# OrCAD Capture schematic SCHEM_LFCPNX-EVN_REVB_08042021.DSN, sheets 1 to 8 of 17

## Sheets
1 Title Page: title: Title Page; rev: 1.0; note: 305-PD-21-0742
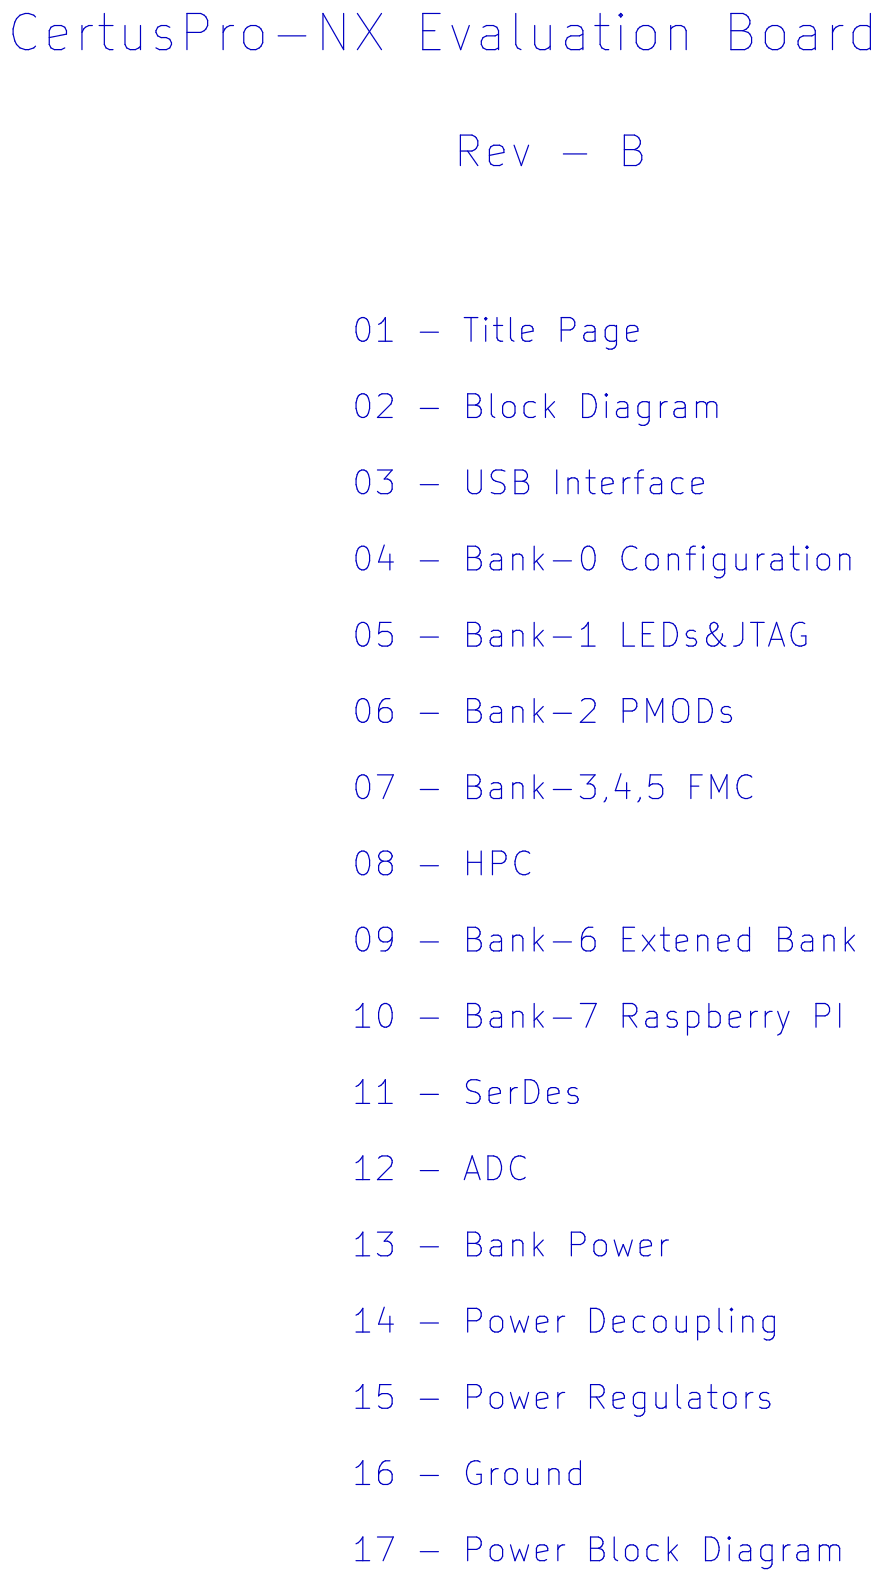
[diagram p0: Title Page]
2 Block Diagram: title: Block Diagram
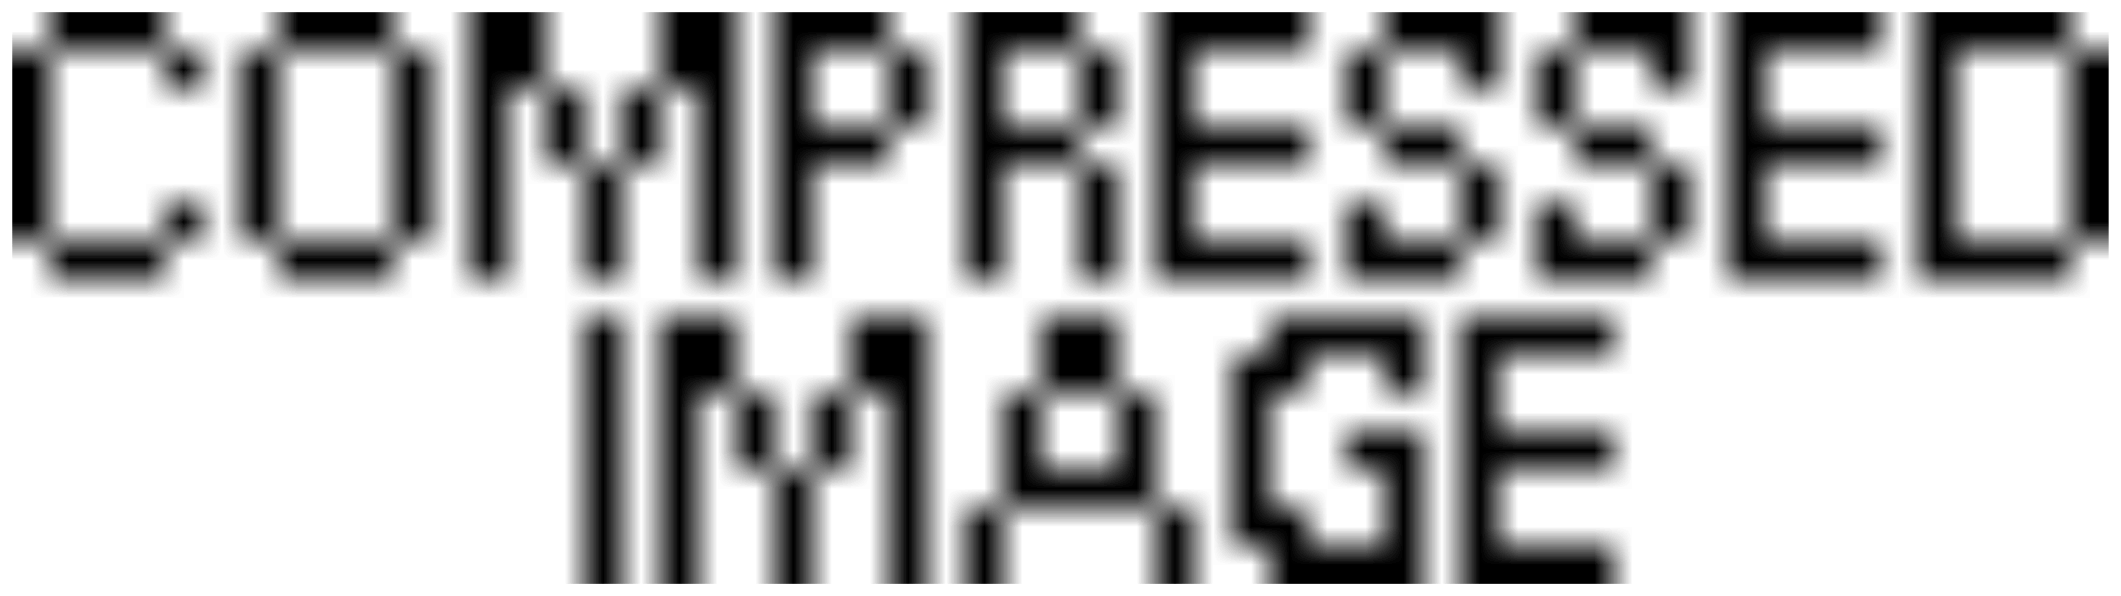
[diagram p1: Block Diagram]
3 USB Interface: size B; title: USB Interface
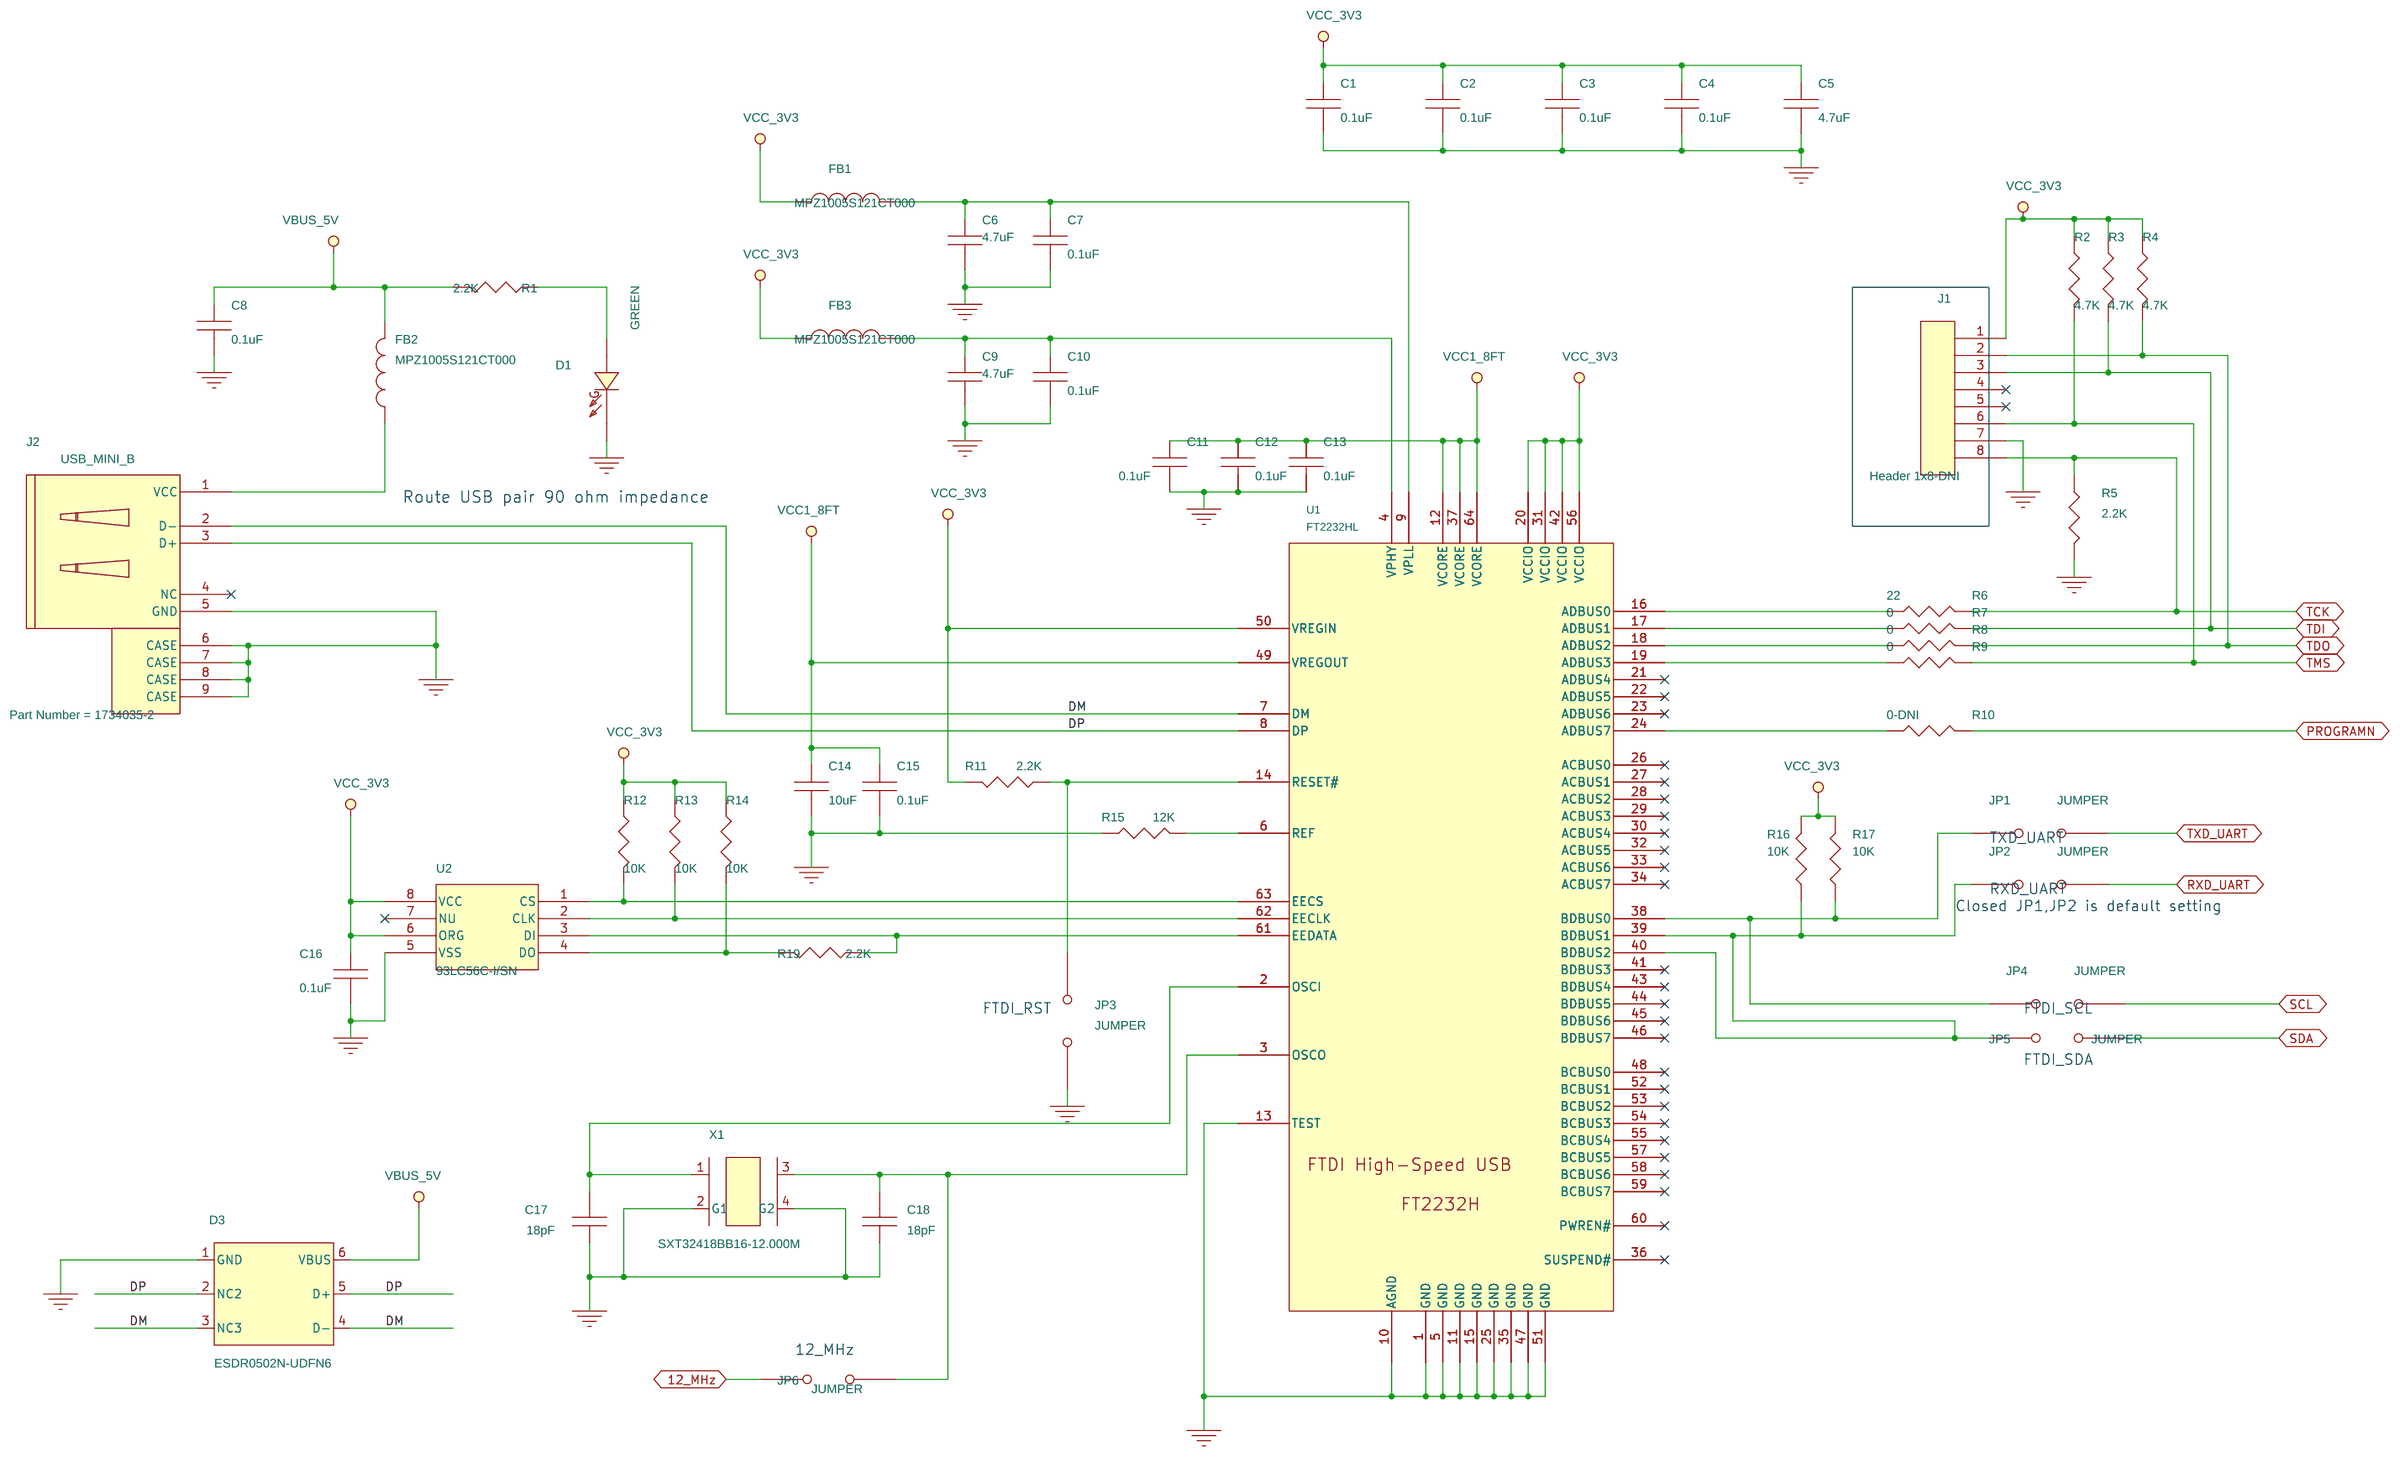
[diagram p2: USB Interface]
4 Bank-0 Configuration: size B; title: Bank-0 Configuration
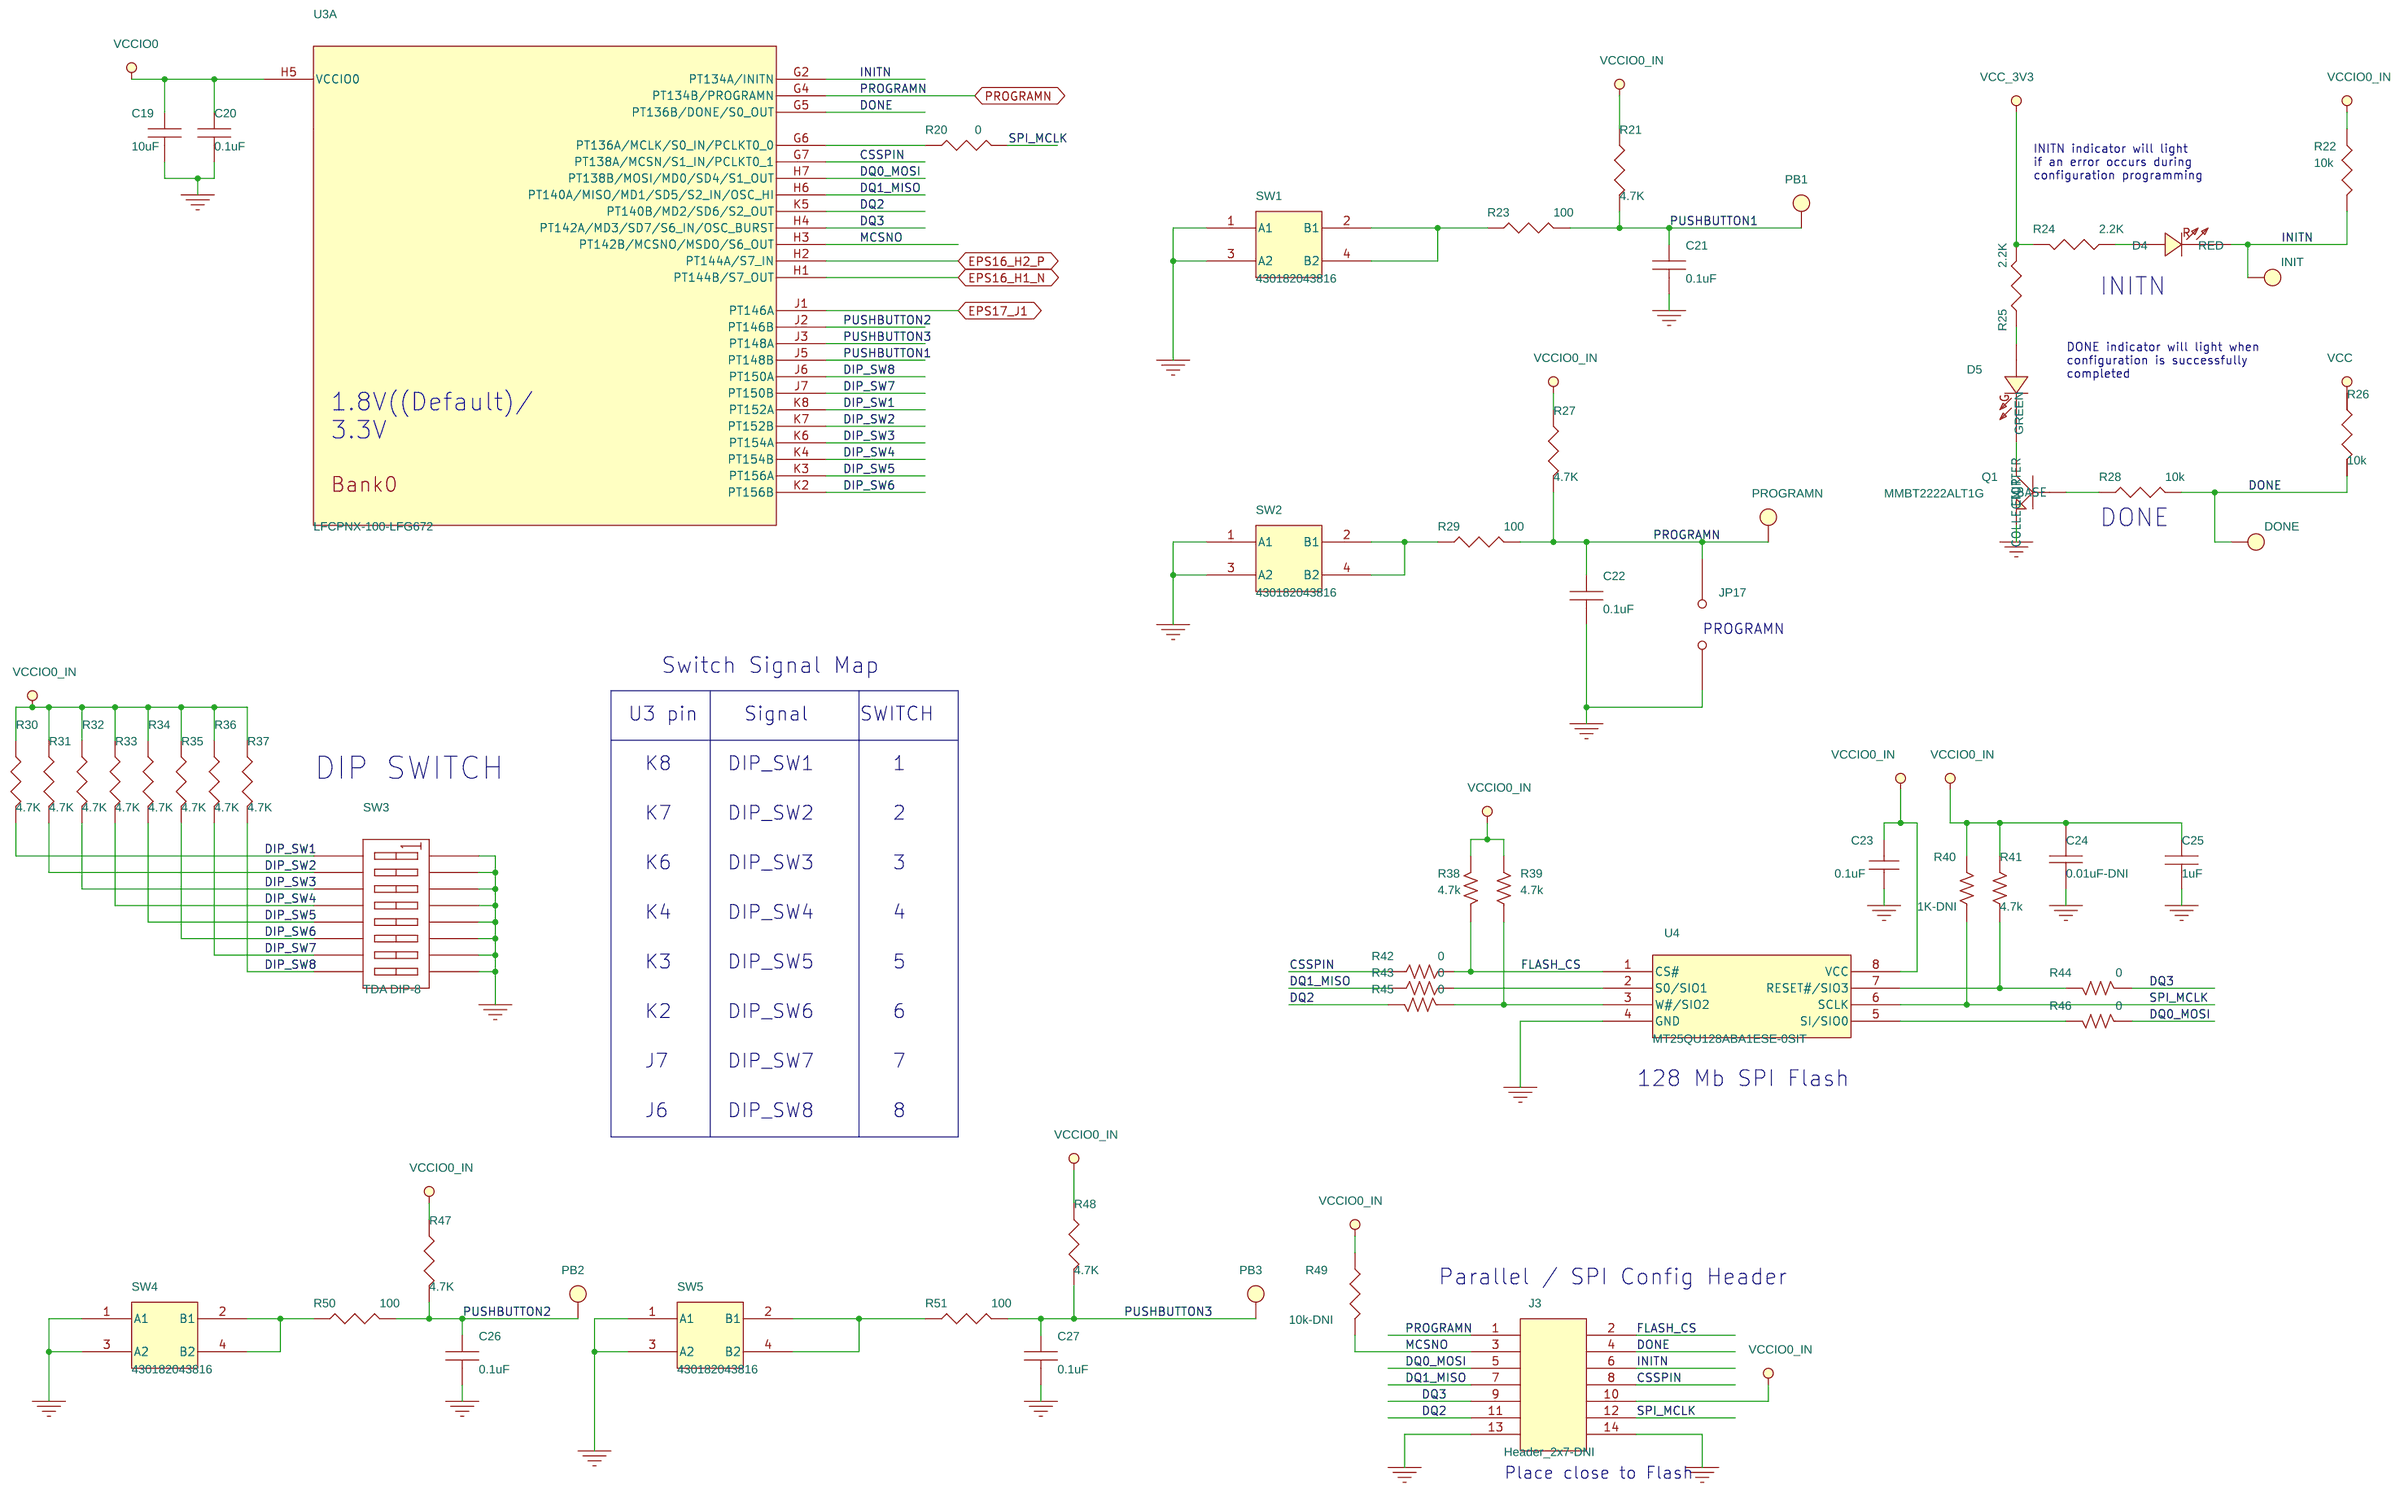
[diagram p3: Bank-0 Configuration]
5 Bank-1 LEDst&JTAG: size B; title: Bank-1 LEDs&JTAG
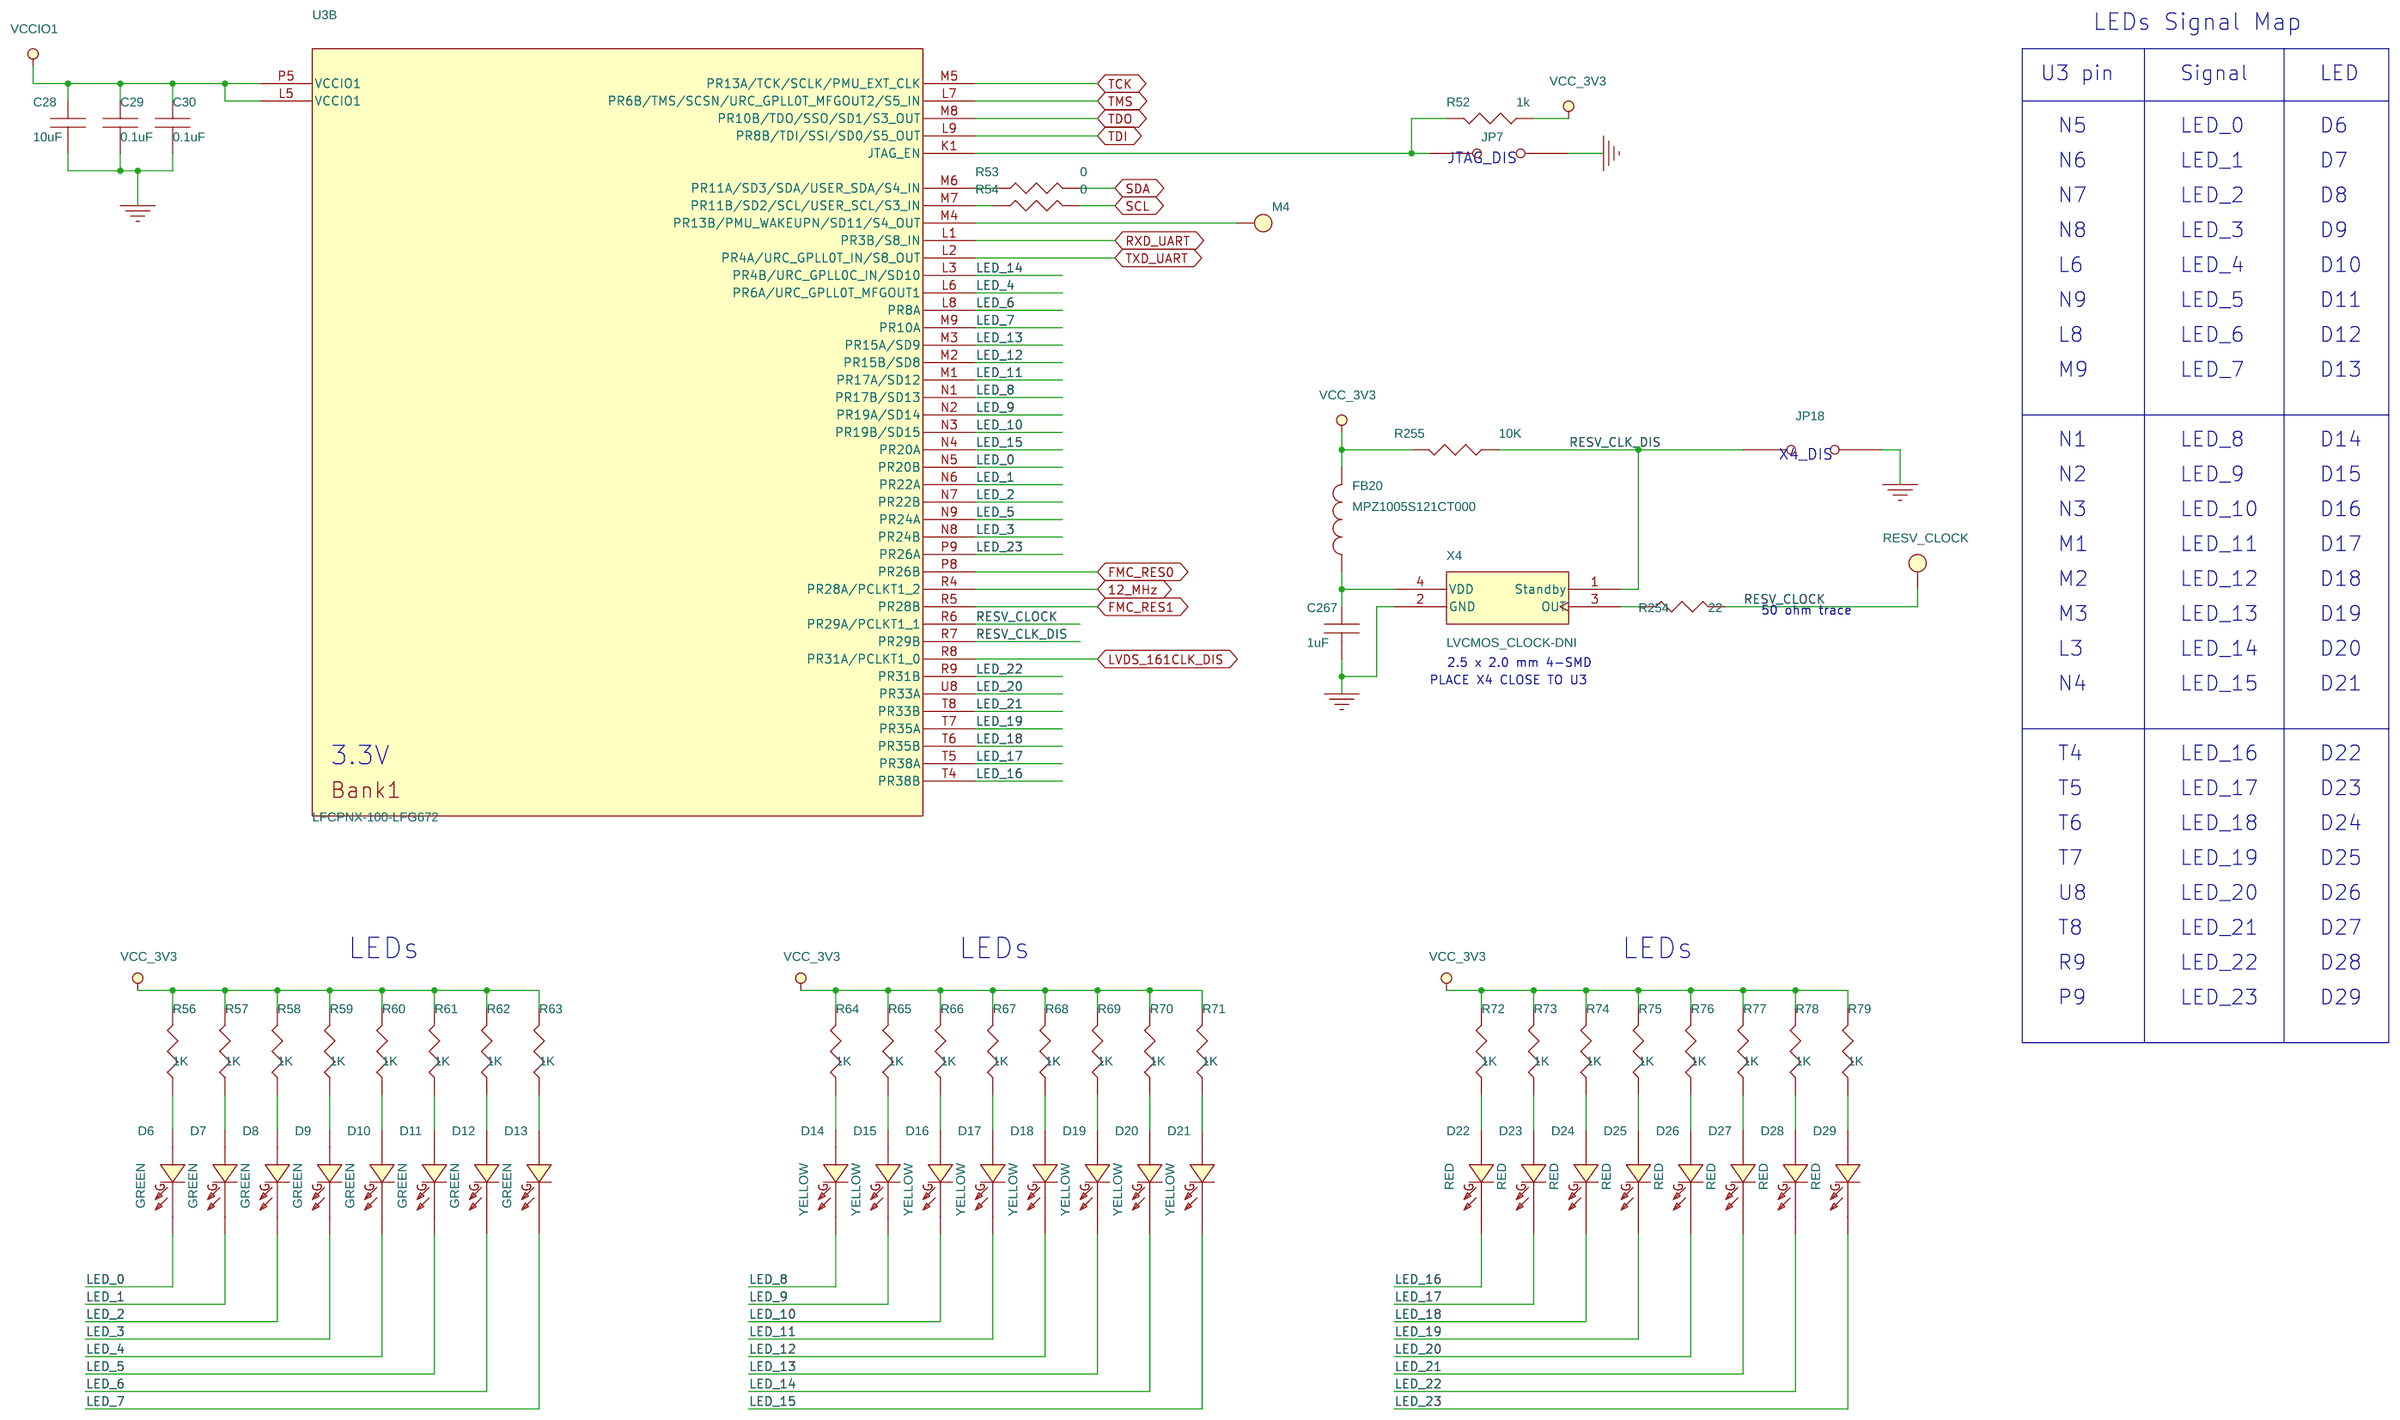
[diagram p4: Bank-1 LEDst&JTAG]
6 Bank-2 PMODs: size B; title: Bank-2 PMODs
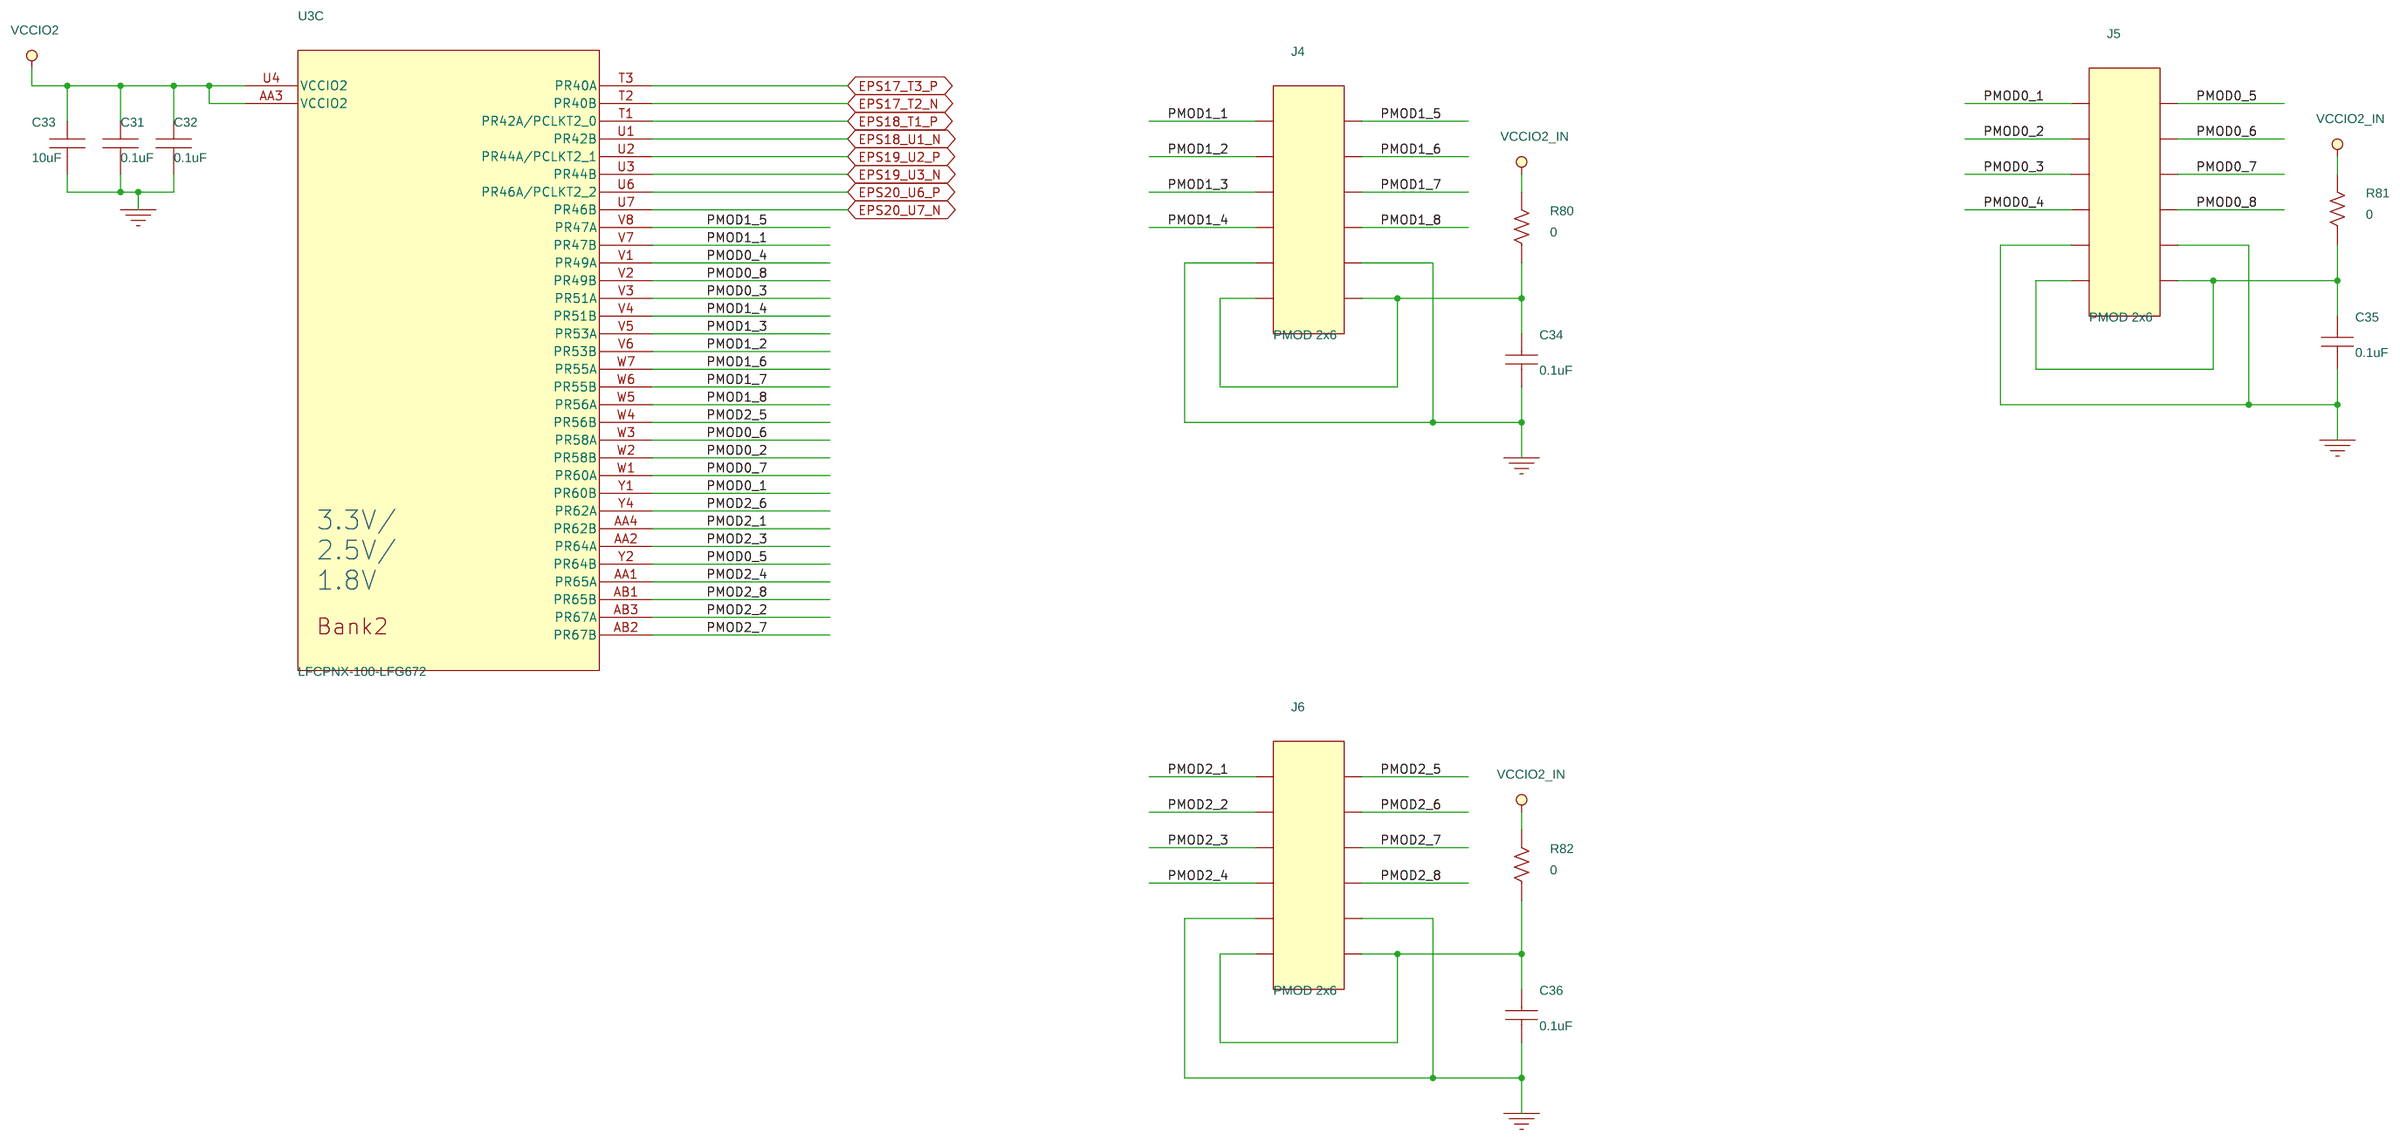
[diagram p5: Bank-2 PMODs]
7 Bank-3,4,5 FMC: size C; title: Bank-3,4,5 FMC
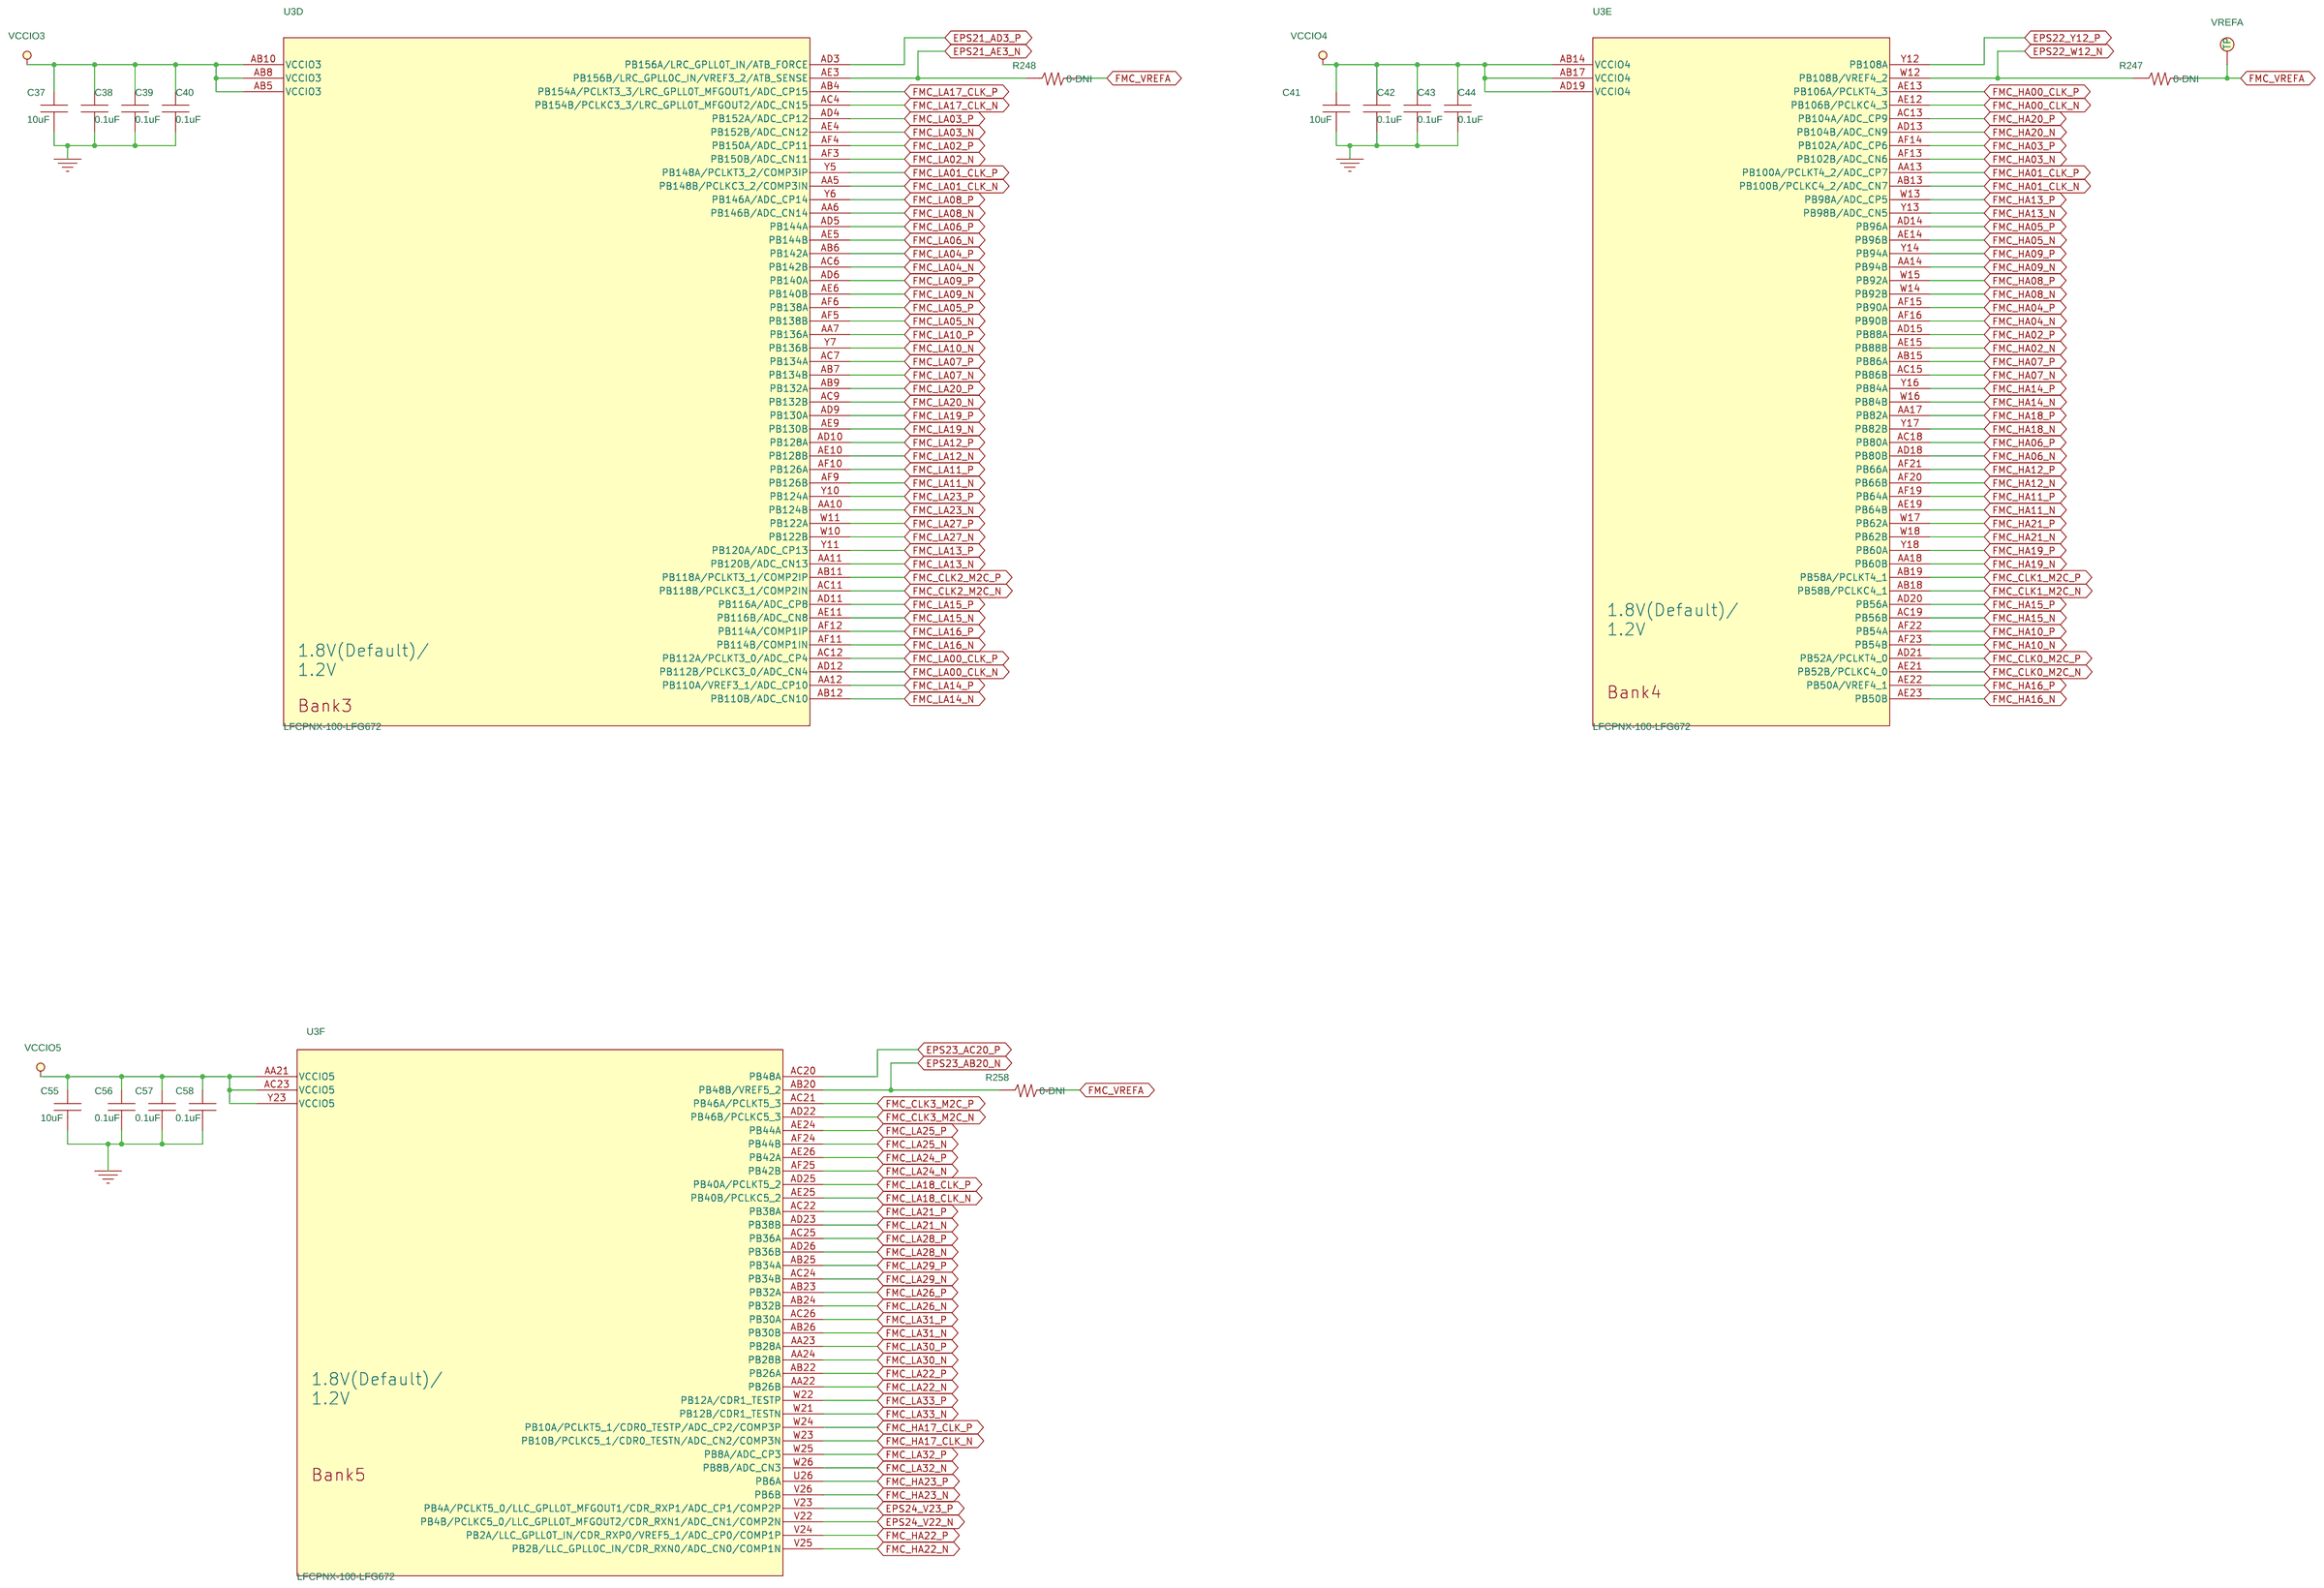
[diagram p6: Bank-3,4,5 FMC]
8 HPC: size C; title: HPC
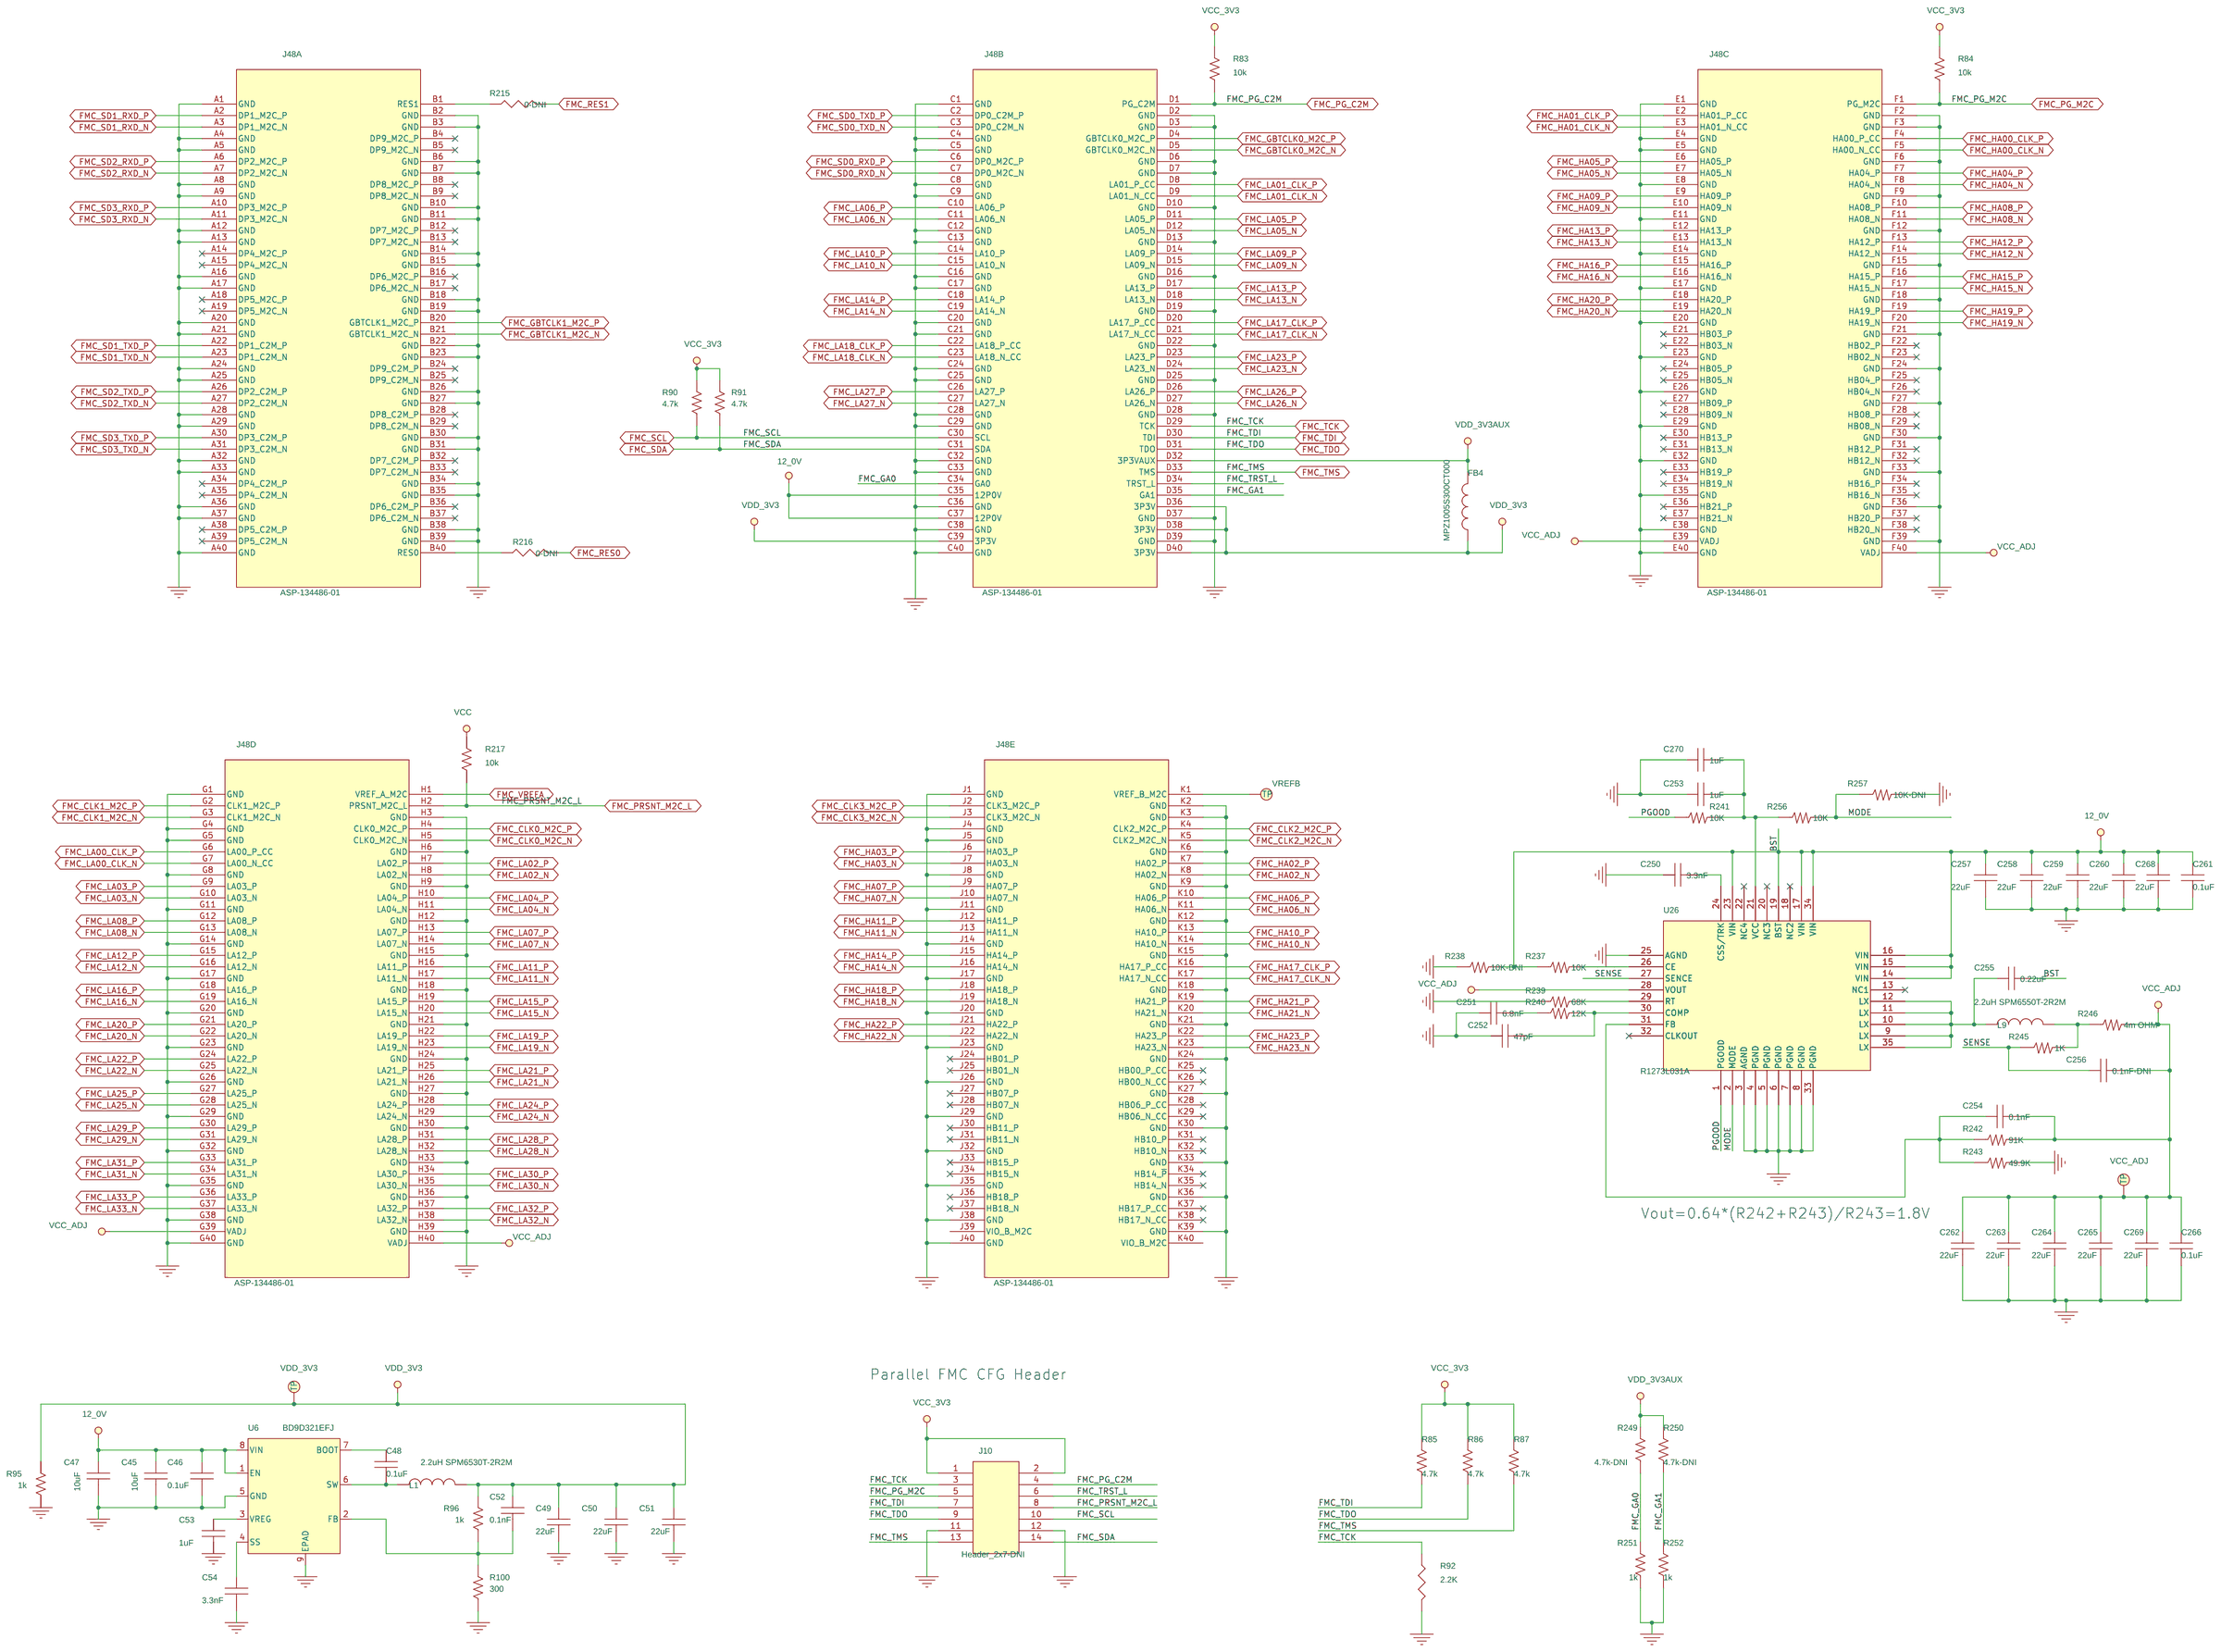
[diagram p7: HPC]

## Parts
sheet Bank-0 Configuration
C19  10uF  [C0402]
C20  0.1uF  [C0201]
C21  0.1uF  [C0201]
C22  0.1uF  [C0201]
C23  0.1uF  [C0201]
C24  0.01uF-DNI  [C0402]
C25  1uF  [C0603]
C26  0.1uF  [C0201]
C27  0.1uF  [C0201]
D4  RED  [APT1608]
D5  GREEN  [APT1608]
DONE  TestPoint  [TP50]
INIT  TestPoint  [TP50]
J3  Header_2x7-DNI  [Header_2x7]
JP17  JUMPER  [Header_1x2]
PB1  TestPoint_SMT  [TPC32]
PB2  TestPoint_SMT  [TPC32]
PB3  TestPoint_SMT  [TPC32]
PROGRAMN  TestPoint_SMT  [TPC32]
Q1  MMBT2222ALT1G  [MMBT2222ALT-1]
R20  0  [R0402]
R21  4.7K  [R0603]
R22  10k  [R0603]
R23  100  [R0402]
R24  2.2K  [R0603]
R25  2.2K  [R0603]
R26  10k  [R0603]
R27  4.7K  [R0603]
R28  10k  [R0603]
R29  100  [R0402]
R30  4.7K  [R0603]
R31  4.7K  [R0603]
R32  4.7K  [R0603]
R33  4.7K  [R0603]
R34  4.7K  [R0603]
R35  4.7K  [R0603]
R36  4.7K  [R0603]
R37  4.7K  [R0603]
R38  4.7k  [R0603]
R39  4.7k  [R0603]
R40  1K-DNI  [R0603]
R41  4.7k  [R0603]
R42  0  [R0402]
R43  0  [R0402]
R44  0  [R0402]
R45  0  [R0402]
R46  0  [R0402]
R47  4.7K  [R0603]
R48  4.7K  [R0603]
R49  10k-DNI  [R0603]
R50  100  [R0402]
R51  100  [R0402]
SW1  430182043816  [430182043816]
SW2  430182043816  [430182043816]
SW3  TDA DIP-8  [TDA08H0SB1]
SW4  430182043816  [430182043816]
SW5  430182043816  [430182043816]
U4  MT25QU128ABA1ESE-0SIT  [SO8_MX25L12833FM2I10G]
sheet Bank-1 LEDst&JTAG
C28  10uF  [C0402]
C29  0.1uF  [C0201]
C30  0.1uF  [C0201]
C267  1uF  [C0603]
D6  GREEN  [APT1608]
D7  GREEN  [APT1608]
D8  GREEN  [APT1608]
D9  GREEN  [APT1608]
D10  GREEN  [APT1608]
D11  GREEN  [APT1608]
D12  GREEN  [APT1608]
D13  GREEN  [APT1608]
D14  YELLOW  [APT1608]
D15  YELLOW  [APT1608]
D16  YELLOW  [APT1608]
D17  YELLOW  [APT1608]
D18  YELLOW  [APT1608]
D19  YELLOW  [APT1608]
D20  YELLOW  [APT1608]
D21  YELLOW  [APT1608]
D22  RED  [APT1608]
D23  RED  [APT1608]
D24  RED  [APT1608]
D25  RED  [APT1608]
D26  RED  [APT1608]
D27  RED  [APT1608]
D28  RED  [APT1608]
D29  RED  [APT1608]
FB20  MPZ1005S121CT000  [FB0402]
JP7  JUMPER  [Header_1x2]
JP18  JUMPER  [Header_1x2]
M4  TestPoint_SMT  [TPC32]
R52  1k  [R0603]
R53  0  [R0402]
R54  0  [R0402]
R56  1K  [R0603]
R57  1K  [R0603]
R58  1K  [R0603]
R59  1K  [R0603]
R60  1K  [R0603]
R61  1K  [R0603]
R62  1K  [R0603]
R63  1K  [R0603]
R64  1K  [R0603]
R65  1K  [R0603]
R66  1K  [R0603]
R67  1K  [R0603]
R68  1K  [R0603]
R69  1K  [R0603]
R70  1K  [R0603]
R71  1K  [R0603]
R72  1K  [R0603]
R73  1K  [R0603]
R74  1K  [R0603]
R75  1K  [R0603]
R76  1K  [R0603]
R77  1K  [R0603]
R78  1K  [R0603]
R79  1K  [R0603]
R254  22  [R0402]
R255  10K  [R0603]
RESV_CLOCK  TestPoint_SMT  [TPC32]
X4  LVCMOS_CLOCK-DNI  [ASFLMB_125_000MHZ-LR-T]
sheet Bank-2 PMODs
C31  0.1uF  [C0201]
C32  0.1uF  [C0201]
C33  10uF  [C0402]
C34  0.1uF  [C0201]
C35  0.1uF  [C0201]
C36  0.1uF  [C0201]
J4  PMOD 2x6  [PPPC062LJBN-RC]
J5  PMOD 2x6  [PPPC062LJBN-RC]
J6  PMOD 2x6  [PPPC062LJBN-RC]
R80  0  [R0603]
R81  0  [R0603]
R82  0  [R0603]
sheet Bank-3,4,5 FMC
C37  10uF  [C0402]
C38  0.1uF  [C0201]
C39  0.1uF  [C0201]
C40  0.1uF  [C0201]
C41  10uF  [C0402]
C42  0.1uF  [C0201]
C43  0.1uF  [C0201]
C44  0.1uF  [C0201]
C55  10uF  [C0402]
C56  0.1uF  [C0201]
C57  0.1uF  [C0201]
C58  0.1uF  [C0201]
R247  0-DNI  [R0603]
R248  0-DNI  [R0603]
R258  0-DNI  [R0603]
VREFA  TP_S_40_63  [tp_s_40_63]
sheet Bank-7 Raspberry PI
U3  LFCPNX-100-LFG672  [BGA672-1P0]  (sections A,B,C,D,E,F,G,H,I,J,K,L,M,N)
sheet HPC
C45  10uF  [C1206]
C46  0.1uF  [C0201]
C47  10uF  [C1206]
C48  0.1uF  [C0201]
C49  22uF  [C0603]
C50  22uF  [C0603]
C51  22uF  [C0603]
C52  0.1nF  [C0603]
C53  1uF  [C0603]
C54  3.3nF  [C0201]
C250  3.3nF  [C0201]
C251  6.8nF  [C0603]
C252  47pF  [C0603]
C253  1uF  [C0603]
C254  0.1nF  [C0603]
C255  0.22uF  [C0603]
C256  0.1nF-DNI  [C0603]
C257  22uF  [C0805]
C258  22uF  [C0805]
C259  22uF  [C0805]
C260  22uF  [C0805]
C261  0.1uF  [C0201]
C262  22uF  [C0603]
C263  22uF  [C0603]
C264  22uF  [C0603]
C265  22uF  [C0603]
C266  0.1uF  [C0201]
C268  22uF  [C0805]
C269  22uF  [C0603]
C270  1uF  [C0603]
FB4  MPZ1005S300CT000  [FB0402]
J10  Header_2x7-DNI  [Header_2x7]
J48  ASP-134486-01  [ASP-134486-01]  (sections A,B,C,D,E)
L1  2.2uH SPM6530T-2R2M  [SPM6530T-2R2M]
L9  2.2uH SPM6550T-2R2M  [SPM6550T-2R2M]
R83  10k  [R0603]
R84  10k  [R0603]
R85  4.7k  [R0603]
R86  4.7k  [R0603]
R87  4.7k  [R0603]
R90  4.7k  [R0603]
R91  4.7k  [R0603]
R92  2.2K  [R0603]
R95  1k  [R0603]
R96  1k  [R0603]
R100  300  [R0402]
R215  0-DNI  [R0603]
R216  0-DNI  [R0603]
R217  10k  [R0603]
R237  10K  [R0603]
R238  10K-DNI  [R0603]
R239  68K  [R0603]
R240  12K  [R0603]
R241  10K  [R0603]
R242  91K  [R0603]
R243  49.9K  [R0603]
R245  1K  [R0603]
R246  4m OHM  [R1206]
R249  4.7k-DNI  [R0603]
R250  4.7k-DNI  [R0603]
R251  1k  [R0603]
R252  1k  [R0603]
R256  10K  [R0603]
R257  10K-DNI  [R0603]
U6  BD9D321EFJ  [HTSOP_8_BD9D321]
U26  R1273L031A  [QFN0505_32B]
VCC_ADJ  TP_S_40_63  [tp_s_40_63]
VDD_3V3  TP_S_40_63  [tp_s_40_63]
VREFB  TP_S_40_63  [tp_s_40_63]
sheet USB Interface
C1  0.1uF  [C0201]
C2  0.1uF  [C0201]
C3  0.1uF  [C0201]
C4  0.1uF  [C0201]
C5  4.7uF  [C0603]
C6  4.7uF  [C0603]
C7  0.1uF  [C0201]
C8  0.1uF  [C0201]
C9  4.7uF  [C0603]
C10  0.1uF  [C0201]
C11  0.1uF  [C0201]
C12  0.1uF  [C0201]
C13  0.1uF  [C0201]
C14  10uF  [C0402]
C15  0.1uF  [C0201]
C16  0.1uF  [C0201]
C17  18pF  [C0402]
C18  18pF  [C0402]
D1  GREEN  [APT1608]
D3  ESDR0502N-UDFN6  [UDFN6_040]
FB1  MPZ1005S121CT000  [FB0402]
FB2  MPZ1005S121CT000  [FB0402]
FB3  MPZ1005S121CT000  [FB0402]
J1  Header 1x8-DNI  [hdr_amp_87220_8_1x8_100]
J2  USB_MINI_B  [USB_MINI_B-1734035-2]
JP1  JUMPER  [Header_1x2]
JP2  JUMPER  [Header_1x2]
JP3  JUMPER  [Header_1x2]
JP4  JUMPER  [Header_1x2]
JP5  JUMPER  [Header_1x2]
JP6  JUMPER  [Header_1x2]
R1  2.2K  [R0603]
R2  4.7K  [R0603]
R3  4.7K  [R0603]
R4  4.7K  [R0603]
R5  2.2K  [R0603]
R6  22  [R0402]
R7  0  [R0402]
R8  0  [R0402]
R9  0  [R0402]
R10  0-DNI  [R0402]
R11  2.2K  [R0603]
R12  10K  [R0603]
R13  10K  [R0603]
R14  10K  [R0603]
R15  12K  [R0603]
R16  10K  [R0603]
R17  10K  [R0603]
R19  2.2K  [R0603]
U1  FT2232HL  [tqfp64_0p5_12p2x12p2_h1p6]
U2  93LC56C-I/SN  [so8_50_244]
X1  SXT32418BB16-12.000M  [xtal_4p_SXT32418BB16_12000M]

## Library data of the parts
C19 C28 C33 C37 C41 C55 = 10uF_0603
C1-C5 C7 C8 C10-C13 C16 C20 C25 C29-C32 C38-C40 C42-C44 C46 C48 C56-C58 = 0u1_0402: CAP CER 0.1UF 25V 10% X5R 0201; Manufacturer: Murata; Manufacturer Part Number: GRM033R61E104KE14J
C15 C21 C22 C26 C27 C261 C266 C267 = 0u1_0402: CAP CER 0.1UF 16V 10% X7R 0402
C23 = CAP_NP: COMPFIXED: NO; COMPGROUP: 0; COMPHEIGHT: 0.000; COMPKEY: NO; COMPLOC: [1820.000,2015.000]; COMPLOCKED: NO; COMPROT: 270; COMPSIDE: TOP; DECOUPLER: NO; FPLIST: SM/C_0402; MEMORY: NO
C24 = CAP_1
D4 = LED-SMT1206_RED_0
D1 D5-D29 = LED-SMT1206_GREEN_1
DONE INIT M4 = T_POINT_R
J3 = Header_2x7: Assy: DNL
JP1-JP7 JP17 JP18 = JUMPER_0
PB1-PB3 PROGRAMN RESV_CLOCK = T_POINT_R: Assy: DNI
Q1 = 2N2222
R20 R53 R54 = R: RES SMD 33 OHM 1% 1/10W 0402; Manufacturer: Panasonic; Manufacturer Part Number: ERJ-2RKF33R0X
R2-R4 R21 R27 R30-R37 R47 R48 = 5k1_0402: RES 4.70K OHM 1/10W 1% 0603 SMD; Digikey P/N: 541-4.70KHTR-ND; Manufacturer: Vishay; Manufacturer Part Number: CRCW06034K70FKEA
R22 R26 R49 = R: RES SMD 10K OHM 1% 1/16W 0402; MFG: Yageo; MFG P/N: RC0402FR-0710KL; Manufacturer: Yageo; Manufacturer Part Number: RC0402FR-0710KL
R23 R29 R50 R51 = RES_10K_1W16_0402_5P: RES SMD 100 OHM 1% 1/10W 0402; Digikey P/N: RMCF0603JT10K0TR-ND; MFG: Pansonic; MFG P/N: ERJ-2RKF1000X; Manufacturer: Pansonic; Manufacturer Part Number: ERJ-2RKF1000X; Wattage: 1/10W
R24 R25 = RES_0: RES SMD 1K OHM 1% 1/10W 0402; Manufacturer: Panasonic; Manufacturer Part Number: ERJ-2RKF1001X
R28 = RES_0: RES SMD 10K OHM 1% 1/16W 0402; MFG: Yageo; MFG P/N: RC0402FR-0710KL; Manufacturer: Yageo; Manufacturer Part Number: RC0402FR-0710KL
R38 R39 R41 R83-R87 R91 R95 R96 R217 R249-R252 = R_v3: RES SMD 4.7K OHM 5% 1/10W 0402; COMPFIXED: NO; COMPGROUP: 0; COMPHEIGHT: 0.000; COMPKEY: NO; COMPLOC: [970.000,1160.000]; COMPLOCKED: NO; COMPROT: 180; COMPSIDE: TOP; DECOUPLER: NO; FPLIST: AX/RC05,SM/R_0603; MEMORY: NO; MFG: Panasonic; MFG P/N: ERJ-2GEJ472X; Manufacturer: Panasonic; Manufacturer Part Number: ERJ-2GEJ472X
R40 = R_v3: RES SMD 1K OHM 1% 1/10W 0402; Assy: DNI; COMPFIXED: NO; COMPGROUP: 0; COMPHEIGHT: 0.000; COMPKEY: NO; COMPLOC: [970.000,1160.000]; COMPLOCKED: NO; COMPROT: 180; COMPSIDE: TOP; DECOUPLER: NO; FPLIST: AX/RC05,SM/R_0603; MEMORY: NO; Manufacturer: Panasonic; Manufacturer Part Number: ERJ-2RKF1001X
R42-R46 = R_v3: RES SMD 0.0OHM JUMPER 1/10W 0402; COMPFIXED: NO; COMPHEIGHT: 0.000; COMPKEY: NO; COMPLOC: [3325.000,1400.000]; COMPLOCKED: NO; COMPROT: 180; COMPSIDE: TOP; DECOUPLER: NO; FPLIST: AX/RC05; MEMORY: NO; Manufacturer: Panasonic; Manufacturer Part Number: ERJ-2GE0R00X
SW1 SW2 SW4 SW5 = EVQP0_0: SWITCH TACTILE SPST-NO 0.05A 12V; Cost Ea/1k: $ 0.11025 (1000-4999), 0.09135 (5000+); Digikey P/N: CKN9112TR-ND; Distributor: Digi-Key; MFG: C&K Components; Manufacturer: C&K Components
SW3 = SW_DIP-8
U4 = N25QxxxA13xF8_0: IC FLASH 128MBIT 104MHZ 8SOP; Manufacturer: Macronix; Manufacturer Part Number: MX25L12833FM2I-10G; Populate: DI
FB1-FB3 FB20 = INDUCTOR_1: FERRITE BEAD 120 OHM 0402 1LN; Manufacturer: TDK Corporation
R52 = RES_100K_1W16_0402_5P: RES 100K OHM 1/10W 1% 0402 SMD; MFG: Panasonic; MFG P/N: ERJ-2RKF1003X; Manufacturer: Panasonic; Manufacturer Part Number: ERJ-2RKF1003X; PART_NUMBER: ERJ-2RKF1003X
R56-R79 = 1k_0402: RES 1K OHM 1/10W 1% 0603 SMD; Digikey P/N: 311-1.00KHRCT-ND; Manufacturer Part Number: RC0603FR-071KL
R254 = 1R_0.25W_0603: Manufacturer: Vishay
R255 = RESISTOR: RES 10K OHM 1/10W 5% 0603
X4 = ASDMB: MEMS OSC XO 125.0000MHZ LVCMOS; Assy: DNI; Manufacturer: Abracon LLC
C34-C36 = C0402C104K4RACTU: CAP CER 0.1UF 25V 10% X5R 0201; Manufacturer: Murata; Manufacturer Part Number: GRM033R61E104KE14J
J4-J6 = SKT2x6_PPPC062LFBN-RC: CONN HDR 12POS 0.1 GOLD PCB R/A; Manufacturer: Sullins
R80-R82 = R_v3: COMPFIXED: NO; COMPHEIGHT: 0.000; COMPKEY: NO; COMPLOC: [970.000,1160.000]; COMPLOCKED: NO; COMPROT: 180; COMPSIDE: TOP; DECOUPLER: NO; FPLIST: AX/RC05,SM/R_0603; MEMORY: NO; Tollerance: 1%
R237-R243 R245-R248 R256-R258 = R_v2: COMPFIXED: 1%
VCC_ADJ VDD_3V3 VREFA VREFB = TP_S_40_63: Assy: DNI
U3 = LFCPNX100K-FFG672
C45 C47 = 10uF_0603: CAP CER 10UF 25V X5R 1206; Manufacturer Part Number: TMK316BJ106KL-T
C49-C51 C262-C265 C269 = 10uF_0603: CAP CER 22UF 10V X5R 0603; Manufacturer: Murata; Manufacturer Part Number: GRM188R61A226ME15D
C52 = 10uF_0603: CAP CER 100PF 50V C0G/NPO 0603; Manufacturer: Yageo; Manufacturer Part Number: CC0603JRNPO9BN101
C53 = 10uF_0603: CAP CER 1UF 25V 10% X7R 0603; Manufacturer Part Number: TMK107B7105KA-T
C54 C250 C254 = 0u1_0402: CAP CER 3300PF 25V X7R 0201; Manufacturer: Murata; Manufacturer Part Number: GRM033R71E332KA12D
C251 = 0u1_0402: CAP CER 6800PF 50V C0G 0603; Digikey P/N: 445-6914-2-ND; Manufacturer: Murata; Manufacturer Part Number: GRM033R71E332KA12D
C252 = 0u1_0402: CAP CER 47PF 50V C0G 0603; Manufacturer: Murata; Manufacturer Part Number: CAP CER 47PF 50V C0G 0603
C253 C270 = 0u1_0402: CAP CER 1UF 25V 10% X7R 0603; Manufacturer: Murata; Manufacturer Part Number: TMK107B7105KA-T
C255 = 0u1_0402: CAP CER 0.22UF 25V X7R 0603; Manufacturer: Murata; Manufacturer Part Number: GCM188R71E224KA55D
C256 = 0u1_0402: CAP CER 100PF 50V C0G/NPO 0603; Manufacturer: Murata; Manufacturer Part Number: CC0603JRNPO9BN101
C257-C260 C268 = 0u1_0402: CAP CER GRT21BR61E226ME13L; Digikey P/N: 490-12389-2-ND; Manufacturer: Murata; Manufacturer Part Number: GRT21BR61E226ME13L
FB4 = INDUCTOR_1: FERRITE BEAD 120 OHM 0402 1LN; Manufacturer: TDK Corporation; Manufacturer Part Number: MPZ1005S121CT000
J10 = Header_2x7
J48 = ASP-134486-01
L1 L9 = INDUCTOR_0
R90 = R_v3: RES SMD 1K OHM 1% 1/10W 0402; COMPFIXED: NO; COMPGROUP: 0; COMPHEIGHT: 0.000; COMPKEY: NO; COMPLOC: [970.000,1160.000]; COMPLOCKED: NO; COMPROT: 180; COMPSIDE: TOP; DECOUPLER: NO; FPLIST: AX/RC05,SM/R_0603; MEMORY: NO; Manufacturer: Panasonic; Manufacturer Part Number: ERJ-2RKF1001X
R5 R11 R92 R215 R216 = 5k1_0402: Digikey P/N: 541-2.20KHTR-ND; Manufacturer: Vishay; Manufacturer Part Number: CRCW06032K20FKEA
R100 = R_v3: RES SMD 300 OHM 1% 1/10W 0402; COMPFIXED: NO; COMPGROUP: 0; COMPHEIGHT: 0.000; COMPKEY: NO; COMPLOC: [970.000,1160.000]; COMPLOCKED: NO; COMPROT: 180; COMPSIDE: TOP; DECOUPLER: NO; FPLIST: AX/RC05,SM/R_0603; MEMORY: NO; MFG: Panasonic; MFG P/N: ERJ-2RKF3000X; Manufacturer: Panasonic; Manufacturer Part Number: ERJ-2RKF3000X
U6 = BD9D321EFJ
U26 = R1273L
C6 C9 = 4u7_0603: CAP CER 4.7UF 6.3V 10% X5R 0603; Digikey P/N: PCC2396CT-ND
C14 = 10uF_0603: CAP CER 10UF 10V 20% X5R 0603
C17 C18 = 0u1_0402: CAP CER 18PF 25V 10% NP0 0402; Digikey P/N: C0402C180K3GACTU-ND; Manufacturer Part Number: C0402C180K3GACTU
D3 = ESDR0502: Manufacturer: Semtech; Manufacturer Part Number: RClamp0524P
J1 = header1x8_100: CONN HEADER 8POS .100 VERT TIN; Assy: DNI; Digikey P/N: WM50017-08-ND; Manufacturer Part Number: 0022284081
J2 = USB_MINI_B_0: CONN RCPT USB2.0 MINI B SMD R/A; COMPFIXED: NO; COMPGROUP: 0; COMPHEIGHT: 0.000; COMPKEY: NO; COMPLOC: [370.000,2590.000]; COMPLOCKED: NO; COMPROT: 270; COMPSIDE: TOP; DECOUPLER: NO; FPLIST: TYPE_B; MEMORY: NO; Manufacturer: TE Connectivity AMP Connectors; Manufacturer Part Number: 1734035-2; Part Number: 1734035-2; Populate: <Populate>
R1 R15 R19 = 10k_0402: RES 12K OHM 1/10W 1% 0603 SMD; Digikey P/N: 311-12.0KHRTR-ND; Manufacturer Part Number: RC0603FR-0712KL; Tolerance: 1%
R6 = 0R_0603: RES SMD 33 OHM 1% 1/10W 0402; Manufacturer: Panasonic; Manufacturer Part Number: ERJ-2RKF33R0X
R7-R9 = 0R_0603: RES 0.0 OHM 1/10W JUMP 0603 SMD
R10 = 0R_0603: RES SMD 1K OHM 1% 1/10W 0603; Assy: DNI; Manufacturer Part Number: RC0603FR-071KL
R12-R14 = RES_10K_1W16_0402_5P: RES 10K OHM 1/10W 5% 0603; Digikey P/N: RMCF0603JT10K0TR-ND; Manufacturer: Stackpole Electronics Inc; Manufacturer Part Number: RMCF0603JT10K0; Wattage: 1/10W
R16 R17 = RESISTOR: Populate: <Populate>
U1 = FT2232HL: IC USB HS DUAL UART/FIFO 64-LQFP; Assy: Customer Supplied
U2 = 93LC56_SO8_0: IC EEPROM 2KBIT 3MHZ 8SOIC
X1 = crystal-3p2x2p5: CRYSTAL 12MHZ 18PF SMD; Manufacturer: Suntsu Electronics, Inc.

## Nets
GND: C1.2 C2.2 C3.2 C4.2 C5.2 C6.2 C7.2 C8.2 C9.2 C10.2 C11.2 C12.2 C13.2 C14.2 C15.2 C16.2 C17.1 C18.1 C19.2 C20.2 C21.2 C22.2 C23.1 C24.2 C25.2 C26.2 C27.2 C28.2 C29.2 C30.2 C31.2 C32.2 C33.2 C34.2 C35.2 C36.2 C37.2 C38.2 C39.2 C40.2 C41.2 C42.2 C43.2 C44.2 C45.2 C46.2 C47.2 C49.2 C50.2 C51.2 C53.2 C54.2 C55.2 C56.2 C57.2 C58.2 C250.1 C251.1 C252.1 C253.1 C257.2 C258.2 C259.2 C260.2 C261.2 C262.2 C263.2 C264.2 C265.2 C266.2 C267.2 C268.2 C269.2 C270.1 D1.1(CATHODE) D3.1(GND) J1.7 J2.5(GND) J2.6(CASE) J2.7(CASE) J2.8(CASE) J2.9(CASE) J3.13 J3.14 J4.5 J4.11 J5.5 J5.11 J6.5 J6.11 J10.11 J10.12 J48.A1(GND) J48.A4(GND) J48.A5(GND) J48.A8(GND) J48.A9(GND) J48.A12(GND) J48.A13(GND) J48.A16(GND) J48.A17(GND) J48.A20(GND) J48.A21(GND) J48.A24(GND) J48.A25(GND) J48.A28(GND) J48.A29(GND) J48.A32(GND) J48.A33(GND) J48.A36(GND) J48.A37(GND) J48.A40(GND) J48.B2(GND) J48.B3(GND) J48.B6(GND) J48.B7(GND) J48.B10(GND) J48.B11(GND) J48.B14(GND) J48.B15(GND) J48.B18(GND) J48.B19(GND) J48.B22(GND) J48.B23(GND) J48.B26(GND) J48.B27(GND) J48.B30(GND) J48.B31(GND) J48.B34(GND) J48.B35(GND) J48.B38(GND) J48.B39(GND) J48.C1(GND) J48.C4(GND) J48.C5(GND) J48.C8(GND) J48.C9(GND) J48.C12(GND) J48.C13(GND) J48.C16(GND) J48.C17(GND) J48.C20(GND) J48.C21(GND) J48.C24(GND) J48.C25(GND) J48.C28(GND) J48.C29(GND) J48.C32(GND) J48.C33(GND) J48.C36(GND) J48.C38(GND) J48.C40(GND) J48.D2(GND) J48.D3(GND) J48.D6(GND) J48.D7(GND) J48.D10(GND) J48.D13(GND) J48.D16(GND) J48.D19(GND) J48.D22(GND) J48.D25(GND) J48.D28(GND) J48.D37(GND) J48.D39(GND) J48.E1(GND) J48.E4(GND) J48.E5(GND) J48.E8(GND) J48.E11(GND) J48.E14(GND) J48.E17(GND) J48.E20(GND) J48.E23(GND) J48.E26(GND) J48.E29(GND) J48.E32(GND) J48.E35(GND) J48.E38(GND) J48.E40(GND) J48.F2(GND) J48.F3(GND) J48.F6(GND) J48.F9(GND) J48.F12(GND) J48.F15(GND) J48.F18(GND) J48.F21(GND) J48.F24(GND) J48.F27(GND) J48.F30(GND) J48.F33(GND) J48.F36(GND) J48.F39(GND) J48.G1(GND) J48.G4(GND) J48.G5(GND) J48.G8(GND) J48.G11(GND) J48.G14(GND) J48.G17(GND) J48.G20(GND) J48.G23(GND) J48.G26(GND) J48.G29(GND) J48.G32(GND) J48.G35(GND) J48.G38(GND) J48.G40(GND) J48.H3(GND) J48.H6(GND) J48.H9(GND) J48.H12(GND) J48.H15(GND) J48.H18(GND) J48.H21(GND) J48.H24(GND) J48.H27(GND) J48.H30(GND) J48.H33(GND) J48.H36(GND) J48.H39(GND) J48.J1(GND) J48.J4(GND) J48.J5(GND) J48.J8(GND) J48.J11(GND) J48.J14(GND) J48.J17(GND) J48.J20(GND) J48.J23(GND) J48.J26(GND) J48.J29(GND) J48.J32(GND) J48.J35(GND) J48.J38(GND) J48.J40(GND) J48.K2(GND) J48.K3(GND) J48.K6(GND) J48.K9(GND) J48.K12(GND) J48.K15(GND) J48.K18(GND) J48.K21(GND) J48.K24(GND) J48.K27(GND) J48.K30(GND) J48.K33(GND) J48.K36(GND) J48.K39(GND) JP3.2 JP7.2 JP17.2 JP18.1 Q1.2(EMITTER) R5.2 R15.1 R92.2 R95.1 R100.1 R238.1 R239.1 R243.2 R251.1 R252.1 R257.2 SW1.1(A1) SW1.3(A2) SW2.1(A1) SW2.3(A2) SW3.9(B8) SW3.10(B7) SW3.11(B6) SW3.12(B5) SW3.13(B4) SW3.14(B3) SW3.15(B2) SW3.16(B1) SW4.1(A1) SW4.3(A2) SW5.1(A1) SW5.3(A2) U1.1(GND) U1.5(GND) U1.10(AGND) U1.11(GND) U1.13(TEST) U1.15(GND) U1.25(GND) U1.35(GND) U1.47(GND) U1.51(GND) U2.5(VSS) U4.4(GND) U6.5(GND) U6.9(EPAD) U26.3(AGND) U26.4(PGND) U26.5(PGND) U26.6(PGND) U26.7(PGND) U26.8(PGND) U26.25(AGND) U26.33(PGND) X1.2(G1) X1.4(G2) X4.2(GND) ; also on sheet 9 10 11 12 13 14 15 16
VBUS_5V: C8.1 D3.6(VBUS) FB2.1 R1.2
VCC1_8FT: C11.1 C12.1 C13.1 C14.1 C15.1 U1.12(VCORE) U1.37(VCORE) U1.49(VREGOUT) U1.64(VCORE)
VCC_3V3: C1.1 C2.1 C3.1 C4.1 C5.1 C16.1 FB1.2 FB3.2 FB20.1 J1.1 J10.1 J10.2 R2.1 R3.1 R4.1 R11.2 R12.1 R13.1 R14.1 R16.2 R17.2 R24.2 R25.2 R52.1 R56.2 R57.2 R58.2 R59.2 R60.2 R61.2 R62.2 R63.2 R64.2 R65.2 R66.2 R67.2 R68.2 R69.2 R70.2 R71.2 R72.2 R73.2 R74.2 R75.2 R76.2 R77.2 R78.2 R79.2 R83.2 R84.2 R85.2 R86.2 R87.2 R90.2 R91.2 R217.2 R255.2 U1.20(VCCIO) U1.31(VCCIO) U1.42(VCCIO) U1.50(VREGIN) U1.56(VCCIO) U2.6(ORG) U2.8(VCC) ; also on sheet 10 11 12 13 15
VCC_ADJ: C254.2 C256.2 C262.1 C263.1 C264.1 C265.1 C266.1 C269.1 J48.E39(VADJ) J48.F40(VADJ) J48.G39(VADJ) J48.H40(VADJ) R242.2 R246.2 U26.28(VOUT) VCC_ADJ.1(TP) ; also on sheet 9 13
VCCIO0: C19.1 C20.1 U3.H5(VCCIO0) ; also on sheet 13
VCCIO0_IN: C23.2 C24.1 C25.1 J3.10 R21.1 R22.1 R26.1 R27.1 R30.1 R31.1 R32.1 R33.1 R34.1 R35.1 R36.1 R37.1 R38.2 R39.2 R40.2 R41.2 R47.1 R48.1 R49.1 U4.8(VCC) ; also on sheet 13
VCCIO1: C28.1 C29.1 C30.1 U3.L5(VCCIO1) U3.P5(VCCIO1) ; also on sheet 13
VCCIO2: C31.1 C32.1 C33.1 U3.AA3(VCCIO2) U3.U4(VCCIO2) ; also on sheet 13
VCCIO2_IN: R80.2 R81.2 R82.2 ; also on sheet 13
VCCIO3: C37.1 C38.1 C39.1 C40.1 U3.AB5(VCCIO3) U3.AB8(VCCIO3) U3.AB10(VCCIO3) ; also on sheet 13
VCCIO4: C41.1 C42.1 C43.1 C44.1 U3.AB14(VCCIO4) U3.AB17(VCCIO4) U3.AD19(VCCIO4) ; also on sheet 13
VCCIO5: C55.1 C56.1 C57.1 C58.1 U3.AA21(VCCIO5) U3.AC23(VCCIO5) U3.Y23(VCCIO5) ; also on sheet 13
VDD_3V3: C49.1 C50.1 C51.1 C52.1 FB4.2 J48.C39(3P3V) J48.D36(3P3V) J48.D38(3P3V) J48.D40(3P3V) L1.2 R95.2 R96.2 VDD_3V3.1(TP) ; also on sheet 9
VDD_3V3AUX: FB4.1 J48.D32(3P3VAUX) R249.2 R250.2
12_0V: C45.1 C46.1 C47.1 C257.1 C258.1 C259.1 C260.1 C261.1 C268.1 J48.C35(12P0V) J48.C37(12P0V) R237.1 R238.2 U6.1(EN) U6.8(VIN) U26.14(VIN) U26.15(VIN) U26.16(VIN) U26.17(VIN) U26.23(VIN) U26.34(VIN) ; also on sheet 15
12_MHz: JP6.2 U3.R4(PR28A/PCLKT1_2)
BST: C255.2 U26.19(BST)
CSSPIN: J3.8 R42.1 U3.G7(PT138A/MCSN/S1_IN/PCLKT0_1)
DIP_SW1: R30.2 SW3.1(A1) U3.K8(PT152A)
DIP_SW2: R31.2 SW3.2(A2) U3.K7(PT152B)
DIP_SW3: R32.2 SW3.3(A3) U3.K6(PT154A)
DIP_SW4: R33.2 SW3.4(A4) U3.K4(PT154B)
DIP_SW5: R34.2 SW3.5(A5) U3.K3(PT156A)
DIP_SW6: R35.2 SW3.6(A6) U3.K2(PT156B)
DIP_SW7: R36.2 SW3.7(A7) U3.J7(PT150B)
DIP_SW8: R37.2 SW3.8(A8) U3.J6(PT150A)
DM: D3.3(NC3) D3.4(D-) J2.2(D-) U1.7(DM)
DONE: DONE.1(TP) J3.4 R26.2 R28.2 U3.G5(PT136B/DONE/S0_OUT)
DP: D3.2(NC2) D3.5(D+) J2.3(D+) U1.8(DP)
DQ0_MOSI: J3.5 R46.1 U3.H7(PT138B/MOSI/MD0/SD4/S1_OUT)
DQ1_MISO: J3.7 R43.1 U3.H6(PT140A/MISO/MD1/SD5/S2_IN/OSC_HI)
DQ2: J3.11 R45.2 U3.K5(PT140B/MD2/SD6/S2_OUT)
DQ3: J3.9 R44.1 U3.H4(PT142A/MD3/SD7/S6_IN/OSC_BURST)
EPS16_H1_N: U3.H1(PT144B/S7_OUT) ; also on sheet 9
EPS16_H2_P: U3.H2(PT144A/S7_IN) ; also on sheet 9
EPS17_J1: U3.J1(PT146A) ; also on sheet 9
EPS17_T2_N: U3.T2(PR40B) ; also on sheet 9
EPS17_T3_P: U3.T3(PR40A) ; also on sheet 9
EPS18_T1_P: U3.T1(PR42A/PCLKT2_0) ; also on sheet 9
EPS18_U1_N: U3.U1(PR42B) ; also on sheet 9
EPS19_U2_P: U3.U2(PR44A/PCLKT2_1) ; also on sheet 9
EPS19_U3_N: U3.U3(PR44B) ; also on sheet 9
EPS20_U6_P: U3.U6(PR46A/PCLKT2_2) ; also on sheet 9
EPS20_U7_N: U3.U7(PR46B) ; also on sheet 9
EPS21_AD3_P: U3.AD3(PB156A/LRC_GPLL0T_IN/ATB_FORCE) ; also on sheet 9
EPS21_AE3_N: R248.1 U3.AE3(PB156B/LRC_GPLL0C_IN/VREF3_2/ATB_SENSE) ; also on sheet 9
EPS22_W12_N: R247.1 U3.W12(PB108B/VREF4_2) ; also on sheet 9
EPS22_Y12_P: U3.Y12(PB108A) ; also on sheet 9
EPS23_AB20_N: R258.1 U3.AB20(PB48B/VREF5_2) ; also on sheet 9
EPS23_AC20_P: U3.AC20(PB48A) ; also on sheet 9
EPS24_V22_N: U3.V22(PB4B/PCLKC5_0/LLC_GPLL0T_MFGOUT2/CDR_RXN1/ADC_CN1/COMP2N) ; also on sheet 9
EPS24_V23_P: U3.V23(PB4A/PCLKT5_0/LLC_GPLL0T_MFGOUT1/CDR_RXP1/ADC_CP1/COMP2P) ; also on sheet 9
FLASH_CS: J3.2 R38.1 R42.2 U4.1(CS#)
FMC_CLK0_M2C_N: J48.H5(CLK0_M2C_N) U3.AE21(PB52B/PCLKC4_0)
FMC_CLK0_M2C_P: J48.H4(CLK0_M2C_P) U3.AD21(PB52A/PCLKT4_0)
FMC_CLK1_M2C_N: J48.G3(CLK1_M2C_N) U3.AB18(PB58B/PCLKC4_1)
FMC_CLK1_M2C_P: J48.G2(CLK1_M2C_P) U3.AB19(PB58A/PCLKT4_1)
FMC_CLK2_M2C_N: J48.K5(CLK2_M2C_N) U3.AC11(PB118B/PCLKC3_1/COMP2IN)
FMC_CLK2_M2C_P: J48.K4(CLK2_M2C_P) U3.AB11(PB118A/PCLKT3_1/COMP2IP)
FMC_CLK3_M2C_N: J48.J3(CLK3_M2C_N) U3.AD22(PB46B/PCLKC5_3)
FMC_CLK3_M2C_P: J48.J2(CLK3_M2C_P) U3.AC21(PB46A/PCLKT5_3)
FMC_GA0: J48.C34(GA0) R249.1 R251.2
FMC_GA1: J48.D35(GA1) R250.1 R252.2
FMC_GBTCLK0_M2C_N: J48.D5(GBTCLK0_M2C_N) ; also on sheet 11
FMC_GBTCLK0_M2C_P: J48.D4(GBTCLK0_M2C_P) ; also on sheet 11
FMC_GBTCLK1_M2C_N: J48.B21(GBTCLK1_M2C_N) ; also on sheet 11
FMC_GBTCLK1_M2C_P: J48.B20(GBTCLK1_M2C_P) ; also on sheet 11
FMC_HA00_CLK_N: J48.F5(HA00_N_CC) U3.AE12(PB106B/PCLKC4_3)
FMC_HA00_CLK_P: J48.F4(HA00_P_CC) U3.AE13(PB106A/PCLKT4_3)
FMC_HA01_CLK_N: J48.E3(HA01_N_CC) U3.AB13(PB100B/PCLKC4_2/ADC_CN7)
FMC_HA01_CLK_P: J48.E2(HA01_P_CC) U3.AA13(PB100A/PCLKT4_2/ADC_CP7)
FMC_HA02_N: J48.K8(HA02_N) U3.AE15(PB88B)
FMC_HA02_P: J48.K7(HA02_P) U3.AD15(PB88A)
FMC_HA03_N: J48.J7(HA03_N) U3.AF13(PB102B/ADC_CN6)
FMC_HA03_P: J48.J6(HA03_P) U3.AF14(PB102A/ADC_CP6)
FMC_HA04_N: J48.F8(HA04_N) U3.AF16(PB90B)
FMC_HA04_P: J48.F7(HA04_P) U3.AF15(PB90A)
FMC_HA05_N: J48.E7(HA05_N) U3.AE14(PB96B)
FMC_HA05_P: J48.E6(HA05_P) U3.AD14(PB96A)
FMC_HA06_N: J48.K11(HA06_N) U3.AD18(PB80B)
FMC_HA06_P: J48.K10(HA06_P) U3.AC18(PB80A)
FMC_HA07_N: J48.J10(HA07_N) U3.AC15(PB86B)
FMC_HA07_P: J48.J9(HA07_P) U3.AB15(PB86A)
FMC_HA08_N: J48.F11(HA08_N) U3.W14(PB92B)
FMC_HA08_P: J48.F10(HA08_P) U3.W15(PB92A)
FMC_HA09_N: J48.E10(HA09_N) U3.AA14(PB94B)
FMC_HA09_P: J48.E9(HA09_P) U3.Y14(PB94A)
FMC_HA10_N: J48.K14(HA10_N) U3.AF23(PB54B)
FMC_HA10_P: J48.K13(HA10_P) U3.AF22(PB54A)
FMC_HA11_N: J48.J13(HA11_N) U3.AE19(PB64B)
FMC_HA11_P: J48.J12(HA11_P) U3.AF19(PB64A)
FMC_HA12_N: J48.F14(HA12_N) U3.AF20(PB66B)
FMC_HA12_P: J48.F13(HA12_P) U3.AF21(PB66A)
FMC_HA13_N: J48.E13(HA13_N) U3.Y13(PB98B/ADC_CN5)
FMC_HA13_P: J48.E12(HA13_P) U3.W13(PB98A/ADC_CP5)
FMC_HA14_N: J48.J16(HA14_N) U3.W16(PB84B)
FMC_HA14_P: J48.J15(HA14_P) U3.Y16(PB84A)
FMC_HA15_N: J48.F17(HA15_N) U3.AC19(PB56B)
FMC_HA15_P: J48.F16(HA15_P) U3.AD20(PB56A)
FMC_HA16_N: J48.E16(HA16_N) U3.AE23(PB50B)
FMC_HA16_P: J48.E15(HA16_P) U3.AE22(PB50A/VREF4_1)
FMC_HA17_CLK_N: J48.K17(HA17_N_CC) U3.W23(PB10B/PCLKC5_1/CDR0_TESTN/ADC_CN2/COMP3N)
FMC_HA17_CLK_P: J48.K16(HA17_P_CC) U3.W24(PB10A/PCLKT5_1/CDR0_TESTP/ADC_CP2/COMP3P)
FMC_HA18_N: J48.J19(HA18_N) U3.Y17(PB82B)
FMC_HA18_P: J48.J18(HA18_P) U3.AA17(PB82A)
FMC_HA19_N: J48.F20(HA19_N) U3.AA18(PB60B)
FMC_HA19_P: J48.F19(HA19_P) U3.Y18(PB60A)
FMC_HA20_N: J48.E19(HA20_N) U3.AD13(PB104B/ADC_CN9)
FMC_HA20_P: J48.E18(HA20_P) U3.AC13(PB104A/ADC_CP9)
FMC_HA21_N: J48.K20(HA21_N) U3.W18(PB62B)
FMC_HA21_P: J48.K19(HA21_P) U3.W17(PB62A)
FMC_HA22_N: J48.J22(HA22_N) U3.V25(PB2B/LLC_GPLL0C_IN/CDR_RXN0/ADC_CN0/COMP1N)
FMC_HA22_P: J48.J21(HA22_P) U3.V24(PB2A/LLC_GPLL0T_IN/CDR_RXP0/VREF5_1/ADC_CP0/COMP1P)
FMC_HA23_N: J48.K23(HA23_N) U3.V26(PB6B)
FMC_HA23_P: J48.K22(HA23_P) U3.U26(PB6A)
FMC_LA00_CLK_N: J48.G7(LA00_N_CC) U3.AD12(PB112B/PCLKC3_0/ADC_CN4)
FMC_LA00_CLK_P: J48.G6(LA00_P_CC) U3.AC12(PB112A/PCLKT3_0/ADC_CP4)
FMC_LA01_CLK_N: J48.D9(LA01_N_CC) U3.AA5(PB148B/PCLKC3_2/COMP3IN)
FMC_LA01_CLK_P: J48.D8(LA01_P_CC) U3.Y5(PB148A/PCLKT3_2/COMP3IP)
FMC_LA02_N: J48.H8(LA02_N) U3.AF3(PB150B/ADC_CN11)
FMC_LA02_P: J48.H7(LA02_P) U3.AF4(PB150A/ADC_CP11)
FMC_LA03_N: J48.G10(LA03_N) U3.AE4(PB152B/ADC_CN12)
FMC_LA03_P: J48.G9(LA03_P) U3.AD4(PB152A/ADC_CP12)
FMC_LA04_N: J48.H11(LA04_N) U3.AC6(PB142B)
FMC_LA04_P: J48.H10(LA04_P) U3.AB6(PB142A)
FMC_LA05_N: J48.D12(LA05_N) U3.AF5(PB138B)
FMC_LA05_P: J48.D11(LA05_P) U3.AF6(PB138A)
FMC_LA06_N: J48.C11(LA06_N) U3.AE5(PB144B)
FMC_LA06_P: J48.C10(LA06_P) U3.AD5(PB144A)
FMC_LA07_N: J48.H14(LA07_N) U3.AB7(PB134B)
FMC_LA07_P: J48.H13(LA07_P) U3.AC7(PB134A)
FMC_LA08_N: J48.G13(LA08_N) U3.AA6(PB146B/ADC_CN14)
FMC_LA08_P: J48.G12(LA08_P) U3.Y6(PB146A/ADC_CP14)
FMC_LA09_N: J48.D15(LA09_N) U3.AE6(PB140B)
FMC_LA09_P: J48.D14(LA09_P) U3.AD6(PB140A)
FMC_LA10_N: J48.C15(LA10_N) U3.Y7(PB136B)
FMC_LA10_P: J48.C14(LA10_P) U3.AA7(PB136A)
FMC_LA11_N: J48.H17(LA11_N) U3.AF9(PB126B)
FMC_LA11_P: J48.H16(LA11_P) U3.AF10(PB126A)
FMC_LA12_N: J48.G16(LA12_N) U3.AE10(PB128B)
FMC_LA12_P: J48.G15(LA12_P) U3.AD10(PB128A)
FMC_LA13_N: J48.D18(LA13_N) U3.AA11(PB120B/ADC_CN13)
FMC_LA13_P: J48.D17(LA13_P) U3.Y11(PB120A/ADC_CP13)
FMC_LA14_N: J48.C19(LA14_N) U3.AB12(PB110B/ADC_CN10)
FMC_LA14_P: J48.C18(LA14_P) U3.AA12(PB110A/VREF3_1/ADC_CP10)
FMC_LA15_N: J48.H20(LA15_N) U3.AE11(PB116B/ADC_CN8)
FMC_LA15_P: J48.H19(LA15_P) U3.AD11(PB116A/ADC_CP8)
FMC_LA16_N: J48.G19(LA16_N) U3.AF11(PB114B/COMP1IN)
FMC_LA16_P: J48.G18(LA16_P) U3.AF12(PB114A/COMP1IP)
FMC_LA17_CLK_N: J48.D21(LA17_N_CC) U3.AC4(PB154B/PCLKC3_3/LRC_GPLL0T_MFGOUT2/ADC_CN15)
FMC_LA17_CLK_P: J48.D20(LA17_P_CC) U3.AB4(PB154A/PCLKT3_3/LRC_GPLL0T_MFGOUT1/ADC_CP15)
FMC_LA18_CLK_N: J48.C23(LA18_N_CC) U3.AE25(PB40B/PCLKC5_2)
FMC_LA18_CLK_P: J48.C22(LA18_P_CC) U3.AD25(PB40A/PCLKT5_2)
FMC_LA19_N: J48.H23(LA19_N) U3.AE9(PB130B)
FMC_LA19_P: J48.H22(LA19_P) U3.AD9(PB130A)
FMC_LA20_N: J48.G22(LA20_N) U3.AC9(PB132B)
FMC_LA20_P: J48.G21(LA20_P) U3.AB9(PB132A)
FMC_LA21_N: J48.H26(LA21_N) U3.AD23(PB38B)
FMC_LA21_P: J48.H25(LA21_P) U3.AC22(PB38A)
FMC_LA22_N: J48.G25(LA22_N) U3.AA22(PB26B)
FMC_LA22_P: J48.G24(LA22_P) U3.AB22(PB26A)
FMC_LA23_N: J48.D24(LA23_N) U3.AA10(PB124B)
FMC_LA23_P: J48.D23(LA23_P) U3.Y10(PB124A)
FMC_LA24_N: J48.H29(LA24_N) U3.AF25(PB42B)
FMC_LA24_P: J48.H28(LA24_P) U3.AE26(PB42A)
FMC_LA25_N: J48.G28(LA25_N) U3.AF24(PB44B)
FMC_LA25_P: J48.G27(LA25_P) U3.AE24(PB44A)
FMC_LA26_N: J48.D27(LA26_N) U3.AB24(PB32B)
FMC_LA26_P: J48.D26(LA26_P) U3.AB23(PB32A)
FMC_LA27_N: J48.C27(LA27_N) U3.W10(PB122B)
FMC_LA27_P: J48.C26(LA27_P) U3.W11(PB122A)
FMC_LA28_N: J48.H32(LA28_N) U3.AD26(PB36B)
FMC_LA28_P: J48.H31(LA28_P) U3.AC25(PB36A)
FMC_LA29_N: J48.G31(LA29_N) U3.AC24(PB34B)
FMC_LA29_P: J48.G30(LA29_P) U3.AB25(PB34A)
FMC_LA30_N: J48.H35(LA30_N) U3.AA24(PB28B)
FMC_LA30_P: J48.H34(LA30_P) U3.AA23(PB28A)
FMC_LA31_N: J48.G34(LA31_N) U3.AB26(PB30B)
FMC_LA31_P: J48.G33(LA31_P) U3.AC26(PB30A)
FMC_LA32_N: J48.H38(LA32_N) U3.W26(PB8B/ADC_CN3)
FMC_LA32_P: J48.H37(LA32_P) U3.W25(PB8A/ADC_CP3)
FMC_LA33_N: J48.G37(LA33_N) U3.W21(PB12B/CDR1_TESTN)
FMC_LA33_P: J48.G36(LA33_P) U3.W22(PB12A/CDR1_TESTP)
FMC_PG_C2M: J10.4 J48.D1(PG_C2M) R83.1 ; also on sheet 10
FMC_PG_M2C: J10.5 J48.F1(PG_M2C) R84.1 ; also on sheet 10
FMC_PRSNT_M2C_L: J10.8 J48.H2(PRSNT_M2C_L) R217.1 ; also on sheet 10
FMC_RES0: R216.2 U3.P8(PR26B)
FMC_RES1: R215.2 U3.R5(PR28B)
FMC_SCL: J10.10 J48.C30(SCL) R90.1 ; also on sheet 10
FMC_SD0_RXD_N: J48.C7(DP0_M2C_N) ; also on sheet 11
FMC_SD0_RXD_P: J48.C6(DP0_M2C_P) ; also on sheet 11
FMC_SD0_TXD_N: J48.C3(DP0_C2M_N) ; also on sheet 11
FMC_SD0_TXD_P: J48.C2(DP0_C2M_P) ; also on sheet 11
FMC_SD1_RXD_N: J48.A3(DP1_M2C_N) ; also on sheet 11
FMC_SD1_RXD_P: J48.A2(DP1_M2C_P) ; also on sheet 11
FMC_SD1_TXD_N: J48.A23(DP1_C2M_N) ; also on sheet 11
FMC_SD1_TXD_P: J48.A22(DP1_C2M_P) ; also on sheet 11
FMC_SD2_RXD_N: J48.A7(DP2_M2C_N) ; also on sheet 11
FMC_SD2_RXD_P: J48.A6(DP2_M2C_P) ; also on sheet 11
FMC_SD2_TXD_N: J48.A27(DP2_C2M_N) ; also on sheet 11
FMC_SD2_TXD_P: J48.A26(DP2_C2M_P) ; also on sheet 11
FMC_SD3_RXD_N: J48.A11(DP3_M2C_N) ; also on sheet 11
FMC_SD3_RXD_P: J48.A10(DP3_M2C_P) ; also on sheet 11
FMC_SD3_TXD_N: J48.A31(DP3_C2M_N) ; also on sheet 11
FMC_SD3_TXD_P: J48.A30(DP3_C2M_P) ; also on sheet 11
FMC_SDA: J10.14 J48.C31(SDA) R91.1 ; also on sheet 10
FMC_TCK: J10.3 J48.D29(TCK) R92.1 ; also on sheet 10
FMC_TDI: J10.7 J48.D30(TDI) R85.1 ; also on sheet 10
FMC_TDO: J10.9 J48.D31(TDO) R86.1 ; also on sheet 10
FMC_TMS: J10.13 J48.D33(TMS) R87.1 ; also on sheet 10
FMC_TRST_L: J10.6 J48.D34(TRST_L)
FMC_VREFA: J48.H1(VREF_A_M2C) R247.2 R248.2 R258.2 VREFA.1(TP)
INITN: D4.1(CATHODE) INIT.1(TP) J3.6 R22.2 U3.G2(PT134A/INITN)
LED_0: D6.1(CATHODE) U3.N5(PR20B)
LED_1: D7.1(CATHODE) U3.N6(PR22A)
LED_2: D8.1(CATHODE) U3.N7(PR22B)
LED_3: D9.1(CATHODE) U3.N8(PR24B)
LED_4: D10.1(CATHODE) U3.L6(PR6A/URC_GPLL0T_MFGOUT1)
LED_5: D11.1(CATHODE) U3.N9(PR24A)
LED_6: D12.1(CATHODE) U3.L8(PR8A)
LED_7: D13.1(CATHODE) U3.M9(PR10A)
LED_8: D14.1(CATHODE) U3.N1(PR17B/SD13)
LED_9: D15.1(CATHODE) U3.N2(PR19A/SD14)
LED_10: D16.1(CATHODE) U3.N3(PR19B/SD15)
LED_11: D17.1(CATHODE) U3.M1(PR17A/SD12)
LED_12: D18.1(CATHODE) U3.M2(PR15B/SD8)
LED_13: D19.1(CATHODE) U3.M3(PR15A/SD9)
LED_14: D20.1(CATHODE) U3.L3(PR4B/URC_GPLL0C_IN/SD10)
LED_15: D21.1(CATHODE) U3.N4(PR20A)
LED_16: D22.1(CATHODE) U3.T4(PR38B)
LED_17: D23.1(CATHODE) U3.T5(PR38A)
LED_18: D24.1(CATHODE) U3.T6(PR35B)
LED_19: D25.1(CATHODE) U3.T7(PR35A)
LED_20: D26.1(CATHODE) U3.U8(PR33A)
LED_21: D27.1(CATHODE) U3.T8(PR33B)
LED_22: D28.1(CATHODE) U3.R9(PR31B)
LED_23: D29.1(CATHODE) U3.P9(PR26A)
LVDS_161CLK_DIS: U3.R8(PR31A/PCLKT1_0) ; also on sheet 11
MCSNO: J3.3 R49.2 U3.H3(PT142B/MCSNO/MSDO/S6_OUT)
MODE: R256.2 R257.1 U26.2(MODE)
PGOOD: R241.1 U26.1(PGOOD)
PMOD0_1: J5.1 U3.Y1(PR60B)
PMOD0_2: J5.2 U3.W2(PR58B)
PMOD0_3: J5.3 U3.V3(PR51A)
PMOD0_4: J5.4 U3.V1(PR49A)
PMOD0_5: J5.7 U3.Y2(PR64B)
PMOD0_6: J5.8 U3.W3(PR58A)
PMOD0_7: J5.9 U3.W1(PR60A)
PMOD0_8: J5.10 U3.V2(PR49B)
PMOD1_1: J4.1 U3.V7(PR47B)
PMOD1_2: J4.2 U3.V6(PR53B)
PMOD1_3: J4.3 U3.V5(PR53A)
PMOD1_4: J4.4 U3.V4(PR51B)
PMOD1_5: J4.7 U3.V8(PR47A)
PMOD1_6: J4.8 U3.W7(PR55A)
PMOD1_7: J4.9 U3.W6(PR55B)
PMOD1_8: J4.10 U3.W5(PR56A)
PMOD2_1: J6.1 U3.AA4(PR62B)
PMOD2_2: J6.2 U3.AB3(PR67A)
PMOD2_3: J6.3 U3.AA2(PR64A)
PMOD2_4: J6.4 U3.AA1(PR65A)
PMOD2_5: J6.7 U3.W4(PR56B)
PMOD2_6: J6.8 U3.Y4(PR62A)
PMOD2_7: J6.9 U3.AB2(PR67B)
PMOD2_8: J6.10 U3.AB1(PR65B)
PROGRAMN: C22.1 J3.1 JP17.1 PROGRAMN.1(TP) R10.2 R27.2 R29.1 U3.G4(PT134B/PROGRAMN)
PUSHBUTTON1: C21.1 PB1.1(TP) R21.2 R23.1 U3.J5(PT148B)
PUSHBUTTON2: C26.1 PB2.1(TP) R47.2 R50.1 U3.J2(PT146B)
PUSHBUTTON3: C27.1 PB3.1(TP) R48.2 R51.1 U3.J3(PT148A)
RESV_CLK_DIS: JP18.2 R255.1 U3.R7(PR29B) X4.1(Standby)
RESV_CLOCK: R254.2 RESV_CLOCK.1(TP) U3.R6(PR29A/PCLKT1_1)
RXD_UART: JP2.2 U3.L1(PR3B/S8_IN)
SCL: JP4.2 R54.1 ; also on sheet 10
SDA: JP5.2 R53.1 ; also on sheet 10
SENSE: C256.1 R245.1 U26.27(SENCE)
SPI_MCLK: J3.12 R20.1 R40.1 U4.6(SCLK)
TCK: J1.8 R5.1 R6.2 U3.M5(PR13A/TCK/SCLK/PMU_EXT_CLK) ; also on sheet 10
TDI: J1.3 R3.2 R7.2 U3.L9(PR8B/TDI/SSI/SD0/S5_OUT) ; also on sheet 10
TDO: J1.2 R4.2 R8.2 U3.M8(PR10B/TDO/SSO/SD1/S3_OUT) ; also on sheet 10
TMS: J1.6 R2.2 R9.2 U3.L7(PR6B/TMS/SCSN/URC_GPLL0T_MFGOUT2/S5_IN) ; also on sheet 10
TXD_UART: JP1.2 U3.L2(PR4A/URC_GPLL0T_IN/S8_OUT)
VIO_B_M2C: J48.J39(VIO_B_M2C) J48.K40(VIO_B_M2C)
N00911: C6.1 C7.1 FB1.1 U1.9(VPLL)
N00925: C9.1 C10.1 FB3.1 U1.4(VPHY)
N01606: JP3.1 R11.1 U1.14(RESET#)
N01656: R15.2 U1.6(REF)
N02092: R12.2 U1.63(EECS) U2.1(CS)
N02098: R13.2 U1.62(EECLK) U2.2(CLK)
N02124: R19.1 U1.61(EEDATA) U2.3(DI)
N02138: R14.2 R19.2 U2.4(DO)
N02805: C17.2 U1.2(OSCI) X1.1
N02831: C18.2 JP6.1 U1.3(OSCO) X1.3
N03813: R9.1 U1.19(ADBUS3)
N03929: R7.1 U1.17(ADBUS1)
N03953: R8.1 U1.18(ADBUS2)
N16504386: FB2.2 J2.1(VCC)
N16632009: JP2.1 JP5.1 R16.1 U1.39(BDBUS1) U1.40(BDBUS2)
N16632070: JP1.1 JP4.1 R17.1 U1.38(BDBUS0)
N16986163: R39.1 R45.1 U4.3(W#/SIO2)
N16986165: R41.1 R44.2 U4.7(RESET#/SIO3)
N16986190: R46.2 U4.5(SI/SIO0)
N16986210: R43.2 U4.2(S0/SIO1)
N16986368: R20.2 U3.G6(PT136A/MCLK/S0_IN/PCLKT0_0)
N16986967: D5.1(CATHODE) Q1.3(COLLECTOR)
N16986992: D5.2(ANODE) R25.1
N17591276: R10.1 U1.24(ADBUS7)
N17596855: R6.1 U1.16(ADBUS0)
N17693161: Q1.1(BASE) R28.1
N18173175: C34.1 J4.6 J4.12 R80.1
N18173239: C35.1 J5.6 J5.12 R81.1
N18281009: JP7.1 R52.2 U3.K1(JTAG_EN)
N18595602: D1.2(ANODE) R1.1
N19482392: D4.2(ANODE) R24.1
N19890586: M4.1(TP) U3.M4(PR13B/PMU_WAKEUPN/SD11/S4_OUT)
N19891304: R53.2 U3.M6(PR11A/SD3/SDA/USER_SDA/S4_IN)
N19891317: R54.2 U3.M7(PR11B/SD2/SCL/USER_SCL/S3_IN)
N19892959: D12.2(ANODE) R62.1
N19892961: D10.2(ANODE) R60.1
N19892963: D7.2(ANODE) R57.1
N19892965: D6.2(ANODE) R56.1
N19892967: D13.2(ANODE) R63.1
N19892969: D11.2(ANODE) R61.1
N19892971: D8.2(ANODE) R58.1
N19892973: D9.2(ANODE) R59.1
N19893443: D20.2(ANODE) R70.1
N19893461: D18.2(ANODE) R68.1
N19893463: D15.2(ANODE) R65.1
N19893465: D14.2(ANODE) R64.1
N19893467: D21.2(ANODE) R71.1
N19893469: D19.2(ANODE) R69.1
N19893471: D16.2(ANODE) R66.1
N19893473: D17.2(ANODE) R67.1
N19894723: D28.2(ANODE) R78.1
N19894733: D26.2(ANODE) R76.1
N19894735: D23.2(ANODE) R73.1
N19894737: D22.2(ANODE) R72.1
N19894739: D29.2(ANODE) R79.1
N19894741: D27.2(ANODE) R77.1
N19894743: D24.2(ANODE) R74.1
N19894753: D25.2(ANODE) R75.1
N19901219: C36.1 J6.6 J6.12 R82.1
N19905771: R50.2 SW4.2(B1) SW4.4(B2)
N19905824: R51.2 SW5.2(B1) SW5.4(B2)
N19906988: R23.2 SW1.2(B1) SW1.4(B2)
N19907225: R29.2 SW2.2(B1) SW2.4(B2)
N20181777: C52.2 R96.1 R100.2 U6.2(FB)
N20181835: C48.1 U6.7(BOOT)
N20181965: C54.1 U6.4(SS)
N20181967: C53.1 U6.3(VREG)
N20182036: C48.2 L1.1 U6.6(SW)
N20325017: J48.B1(RES1) R215.1
N20325029: J48.B40(RES0) R216.1
N20326103: J48.K1(VREF_B_M2C) VREFB.1(TP)
N20360992: C255.1 L9.1 U26.9(LX) U26.10(LX) U26.11(LX) U26.12(LX) U26.35(LX)
N20366079: R237.2 U26.26(CE)
N20371109: R239.2 U26.29(RT)
N20373505: C250.2 U26.24(CSS/TRK)
N20374476: C252.2 R240.2 U26.30(COMP)
N20374523: C251.2 R240.1
N20378873: C253.2 C270.2 R241.2 R256.1 U26.21(VCC)
N20381683: C254.1 R242.1 R243.1 U26.31(FB)
N20386765: L9.2 R245.2 R246.1
N20471123: C267.1 FB20.2 X4.4(VDD)
N20471140: R254.1 X4.3(OUT)

Not connected (* = marked no-connect by the designer): J1 4* 5*; J2 4(NC)*; J48 A14(DP4_M2C_P)* A15(DP4_M2C_N)* A18(DP5_M2C_P)* A19(DP5_M2C_N)* A34(DP4_C2M_P)* A35(DP4_C2M_N)* A38(DP5_C2M_P)* A39(DP5_C2M_N)* B4(DP9_M2C_P)* B5(DP9_M2C_N)* B8(DP8_M2C_P)* B9(DP8_M2C_N)* B12(DP7_M2C_P)* B13(DP7_M2C_N)* B16(DP6_M2C_P)* B17(DP6_M2C_N)* B24(DP9_C2M_P)* B25(DP9_C2M_N)* B28(DP8_C2M_P)* B29(DP8_C2M_N)* B32(DP7_C2M_P)* B33(DP7_C2M_N)* B36(DP6_C2M_P)* B37(DP6_C2M_N)* E21(HB03_P)* E22(HB03_N)* E24(HB05_P)* E25(HB05_N)* E27(HB09_P)* E28(HB09_N)* E30(HB13_P)* E31(HB13_N)* E33(HB19_P)* E34(HB19_N)* E36(HB21_P)* E37(HB21_N)* F22(HB02_P)* F23(HB02_N)* F25(HB04_P)* F26(HB04_N)* F28(HB08_P)* F29(HB08_N)* F31(HB12_P)* F32(HB12_N)* F34(HB16_P)* F35(HB16_N)* F37(HB20_P)* F38(HB20_N)* J24(HB01_P)* J25(HB01_N)* J27(HB07_P)* J28(HB07_N)* J30(HB11_P)* J31(HB11_N)* J33(HB15_P)* J34(HB15_N)* J36(HB18_P)* J37(HB18_N)* K25(HB00_P_CC)* K26(HB00_N_CC)* K28(HB06_P_CC)* K29(HB06_N_CC)* K31(HB10_P)* K32(HB10_N)* K34(HB14_~{P})* K35(HB14_N)* K37(HB17_P_CC)* K38(HB17_N_CC)*; U1 21(ADBUS4)* 22(ADBUS5)* 23(ADBUS6)* 26(ACBUS0)* 27(ACBUS1)* 28(ACBUS2)* 29(ACBUS3)* 30(ACBUS4)* 32(ACBUS5)* 33(ACBUS6)* 34(ACBUS7)* 36(SUSPEND#)* 41(BDBUS3)* 43(BDBUS4)* 44(BDBUS5)* 45(BDBUS6)* 46(BDBUS7)* 48(BCBUS0)* 52(BCBUS1)* 53(BCBUS2)* 54(BCBUS3)* 55(BCBUS4)* 57(BCBUS5)* 58(BCBUS6)* 59(BCBUS7)* 60(PWREN#)*; U2 7(NU)*; U26 13(NC1)* 18(NC2)* 20(NC3)* 22(NC4)* 32(CLKOUT)*

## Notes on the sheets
sheet 1
- CertusPro-NX Evaluation Board
- Rev - B
- 01 - Title Page
  02 - Block Diagram
  03 - USB Interface
  04 - Bank-0 Configuration
  05 - Bank-1 LEDs&JTAG
  06 - Bank-2 PMODs
  07 - Bank-3,4,5 FMC
  08 - HPC
  09 - Bank-6 Extened Bank
  10 - Bank-7 Raspberry PI
  11 - SerDes
  12 - ADC
  13 - Bank Power
  14 - Power Decoupling
  15 - Power Regulators
  16 - Ground
  17 - Power Block Diagram
sheet 3
- Route USB pair 90 ohm impedance
- TXD_UART
- RXD_UART
- Closed JP1,JP2 is default setting
- FTDI_RST
- FTDI_SCL
- FTDI_SDA
- 12_MHz
sheet 4
- INITN indicator will light
  if an error occurs during
  configuration programming
- INITN
- DONE indicator will light when
  configuration is successfully
  completed
- 1.8V((Default)/
  3.3V
- DONE
- PROGRAMN
- Switch Signal Map
- U3 pin
- Signal
- SWITCH
- DIP SWITCH
- K8
- DIP_SW1
- 1
- K7
- DIP_SW2
- 2
- K6
- DIP_SW3
- 3
- K4
- DIP_SW4
- 4
- K3
- DIP_SW5
- 5
- K2
- DIP_SW6
- 6
- J7
- DIP_SW7
- 7
- 128 Mb SPI Flash
- J6
- DIP_SW8
- 8
- Parallel / SPI Config Header
- Place close to Flash
sheet 5
- LEDs Signal Map
- U3 pin
- Signal
- LED
- N5
- LED_0
- D6
- JTAG_DIS
- N6
- LED_1
- D7
- N7
- LED_2
- D8
- N8
- LED_3
- D9
- L6
- LED_4
- D10
- N9
- LED_5
- D11
- L8
- LED_6
- D12
- M9
- LED_7
- D13
- N1
- LED_8
- D14
- X4_DIS
- N2
- LED_9
- D15
- N3
- LED_10
- D16
- M1
- LED_11
- D17
- M2
- LED_12
- D18
- 50 ohm trace
- M3
- LED_13
- D19
- L3
- LED_14
- D20
- 2.5 x 2.0 mm 4-SMD
- PLACE X4 CLOSE TO U3
- N4
- LED_15
- D21
- 3.3V
- T4
- LED_16
- D22
- T5
- LED_17
- D23
- T6
- LED_18
- D24
- T7
- LED_19
- D25
- U8
- LED_20
- D26
- T8
- LED_21
- D27
- LEDs
- LEDs
- LEDs
- R9
- LED_22
- D28
- P9
- LED_23
- D29
sheet 6
- 3.3V/
  2.5V/
  1.8V
sheet 7
- 1.8V(Default)/
  1.2V
- 1.8V(Default)/
  1.2V
- 1.8V(Default)/
  1.2V
sheet 8
- Vout=0.64*(R242+R243)/R243=1.8V
- Parallel FMC CFG Header
